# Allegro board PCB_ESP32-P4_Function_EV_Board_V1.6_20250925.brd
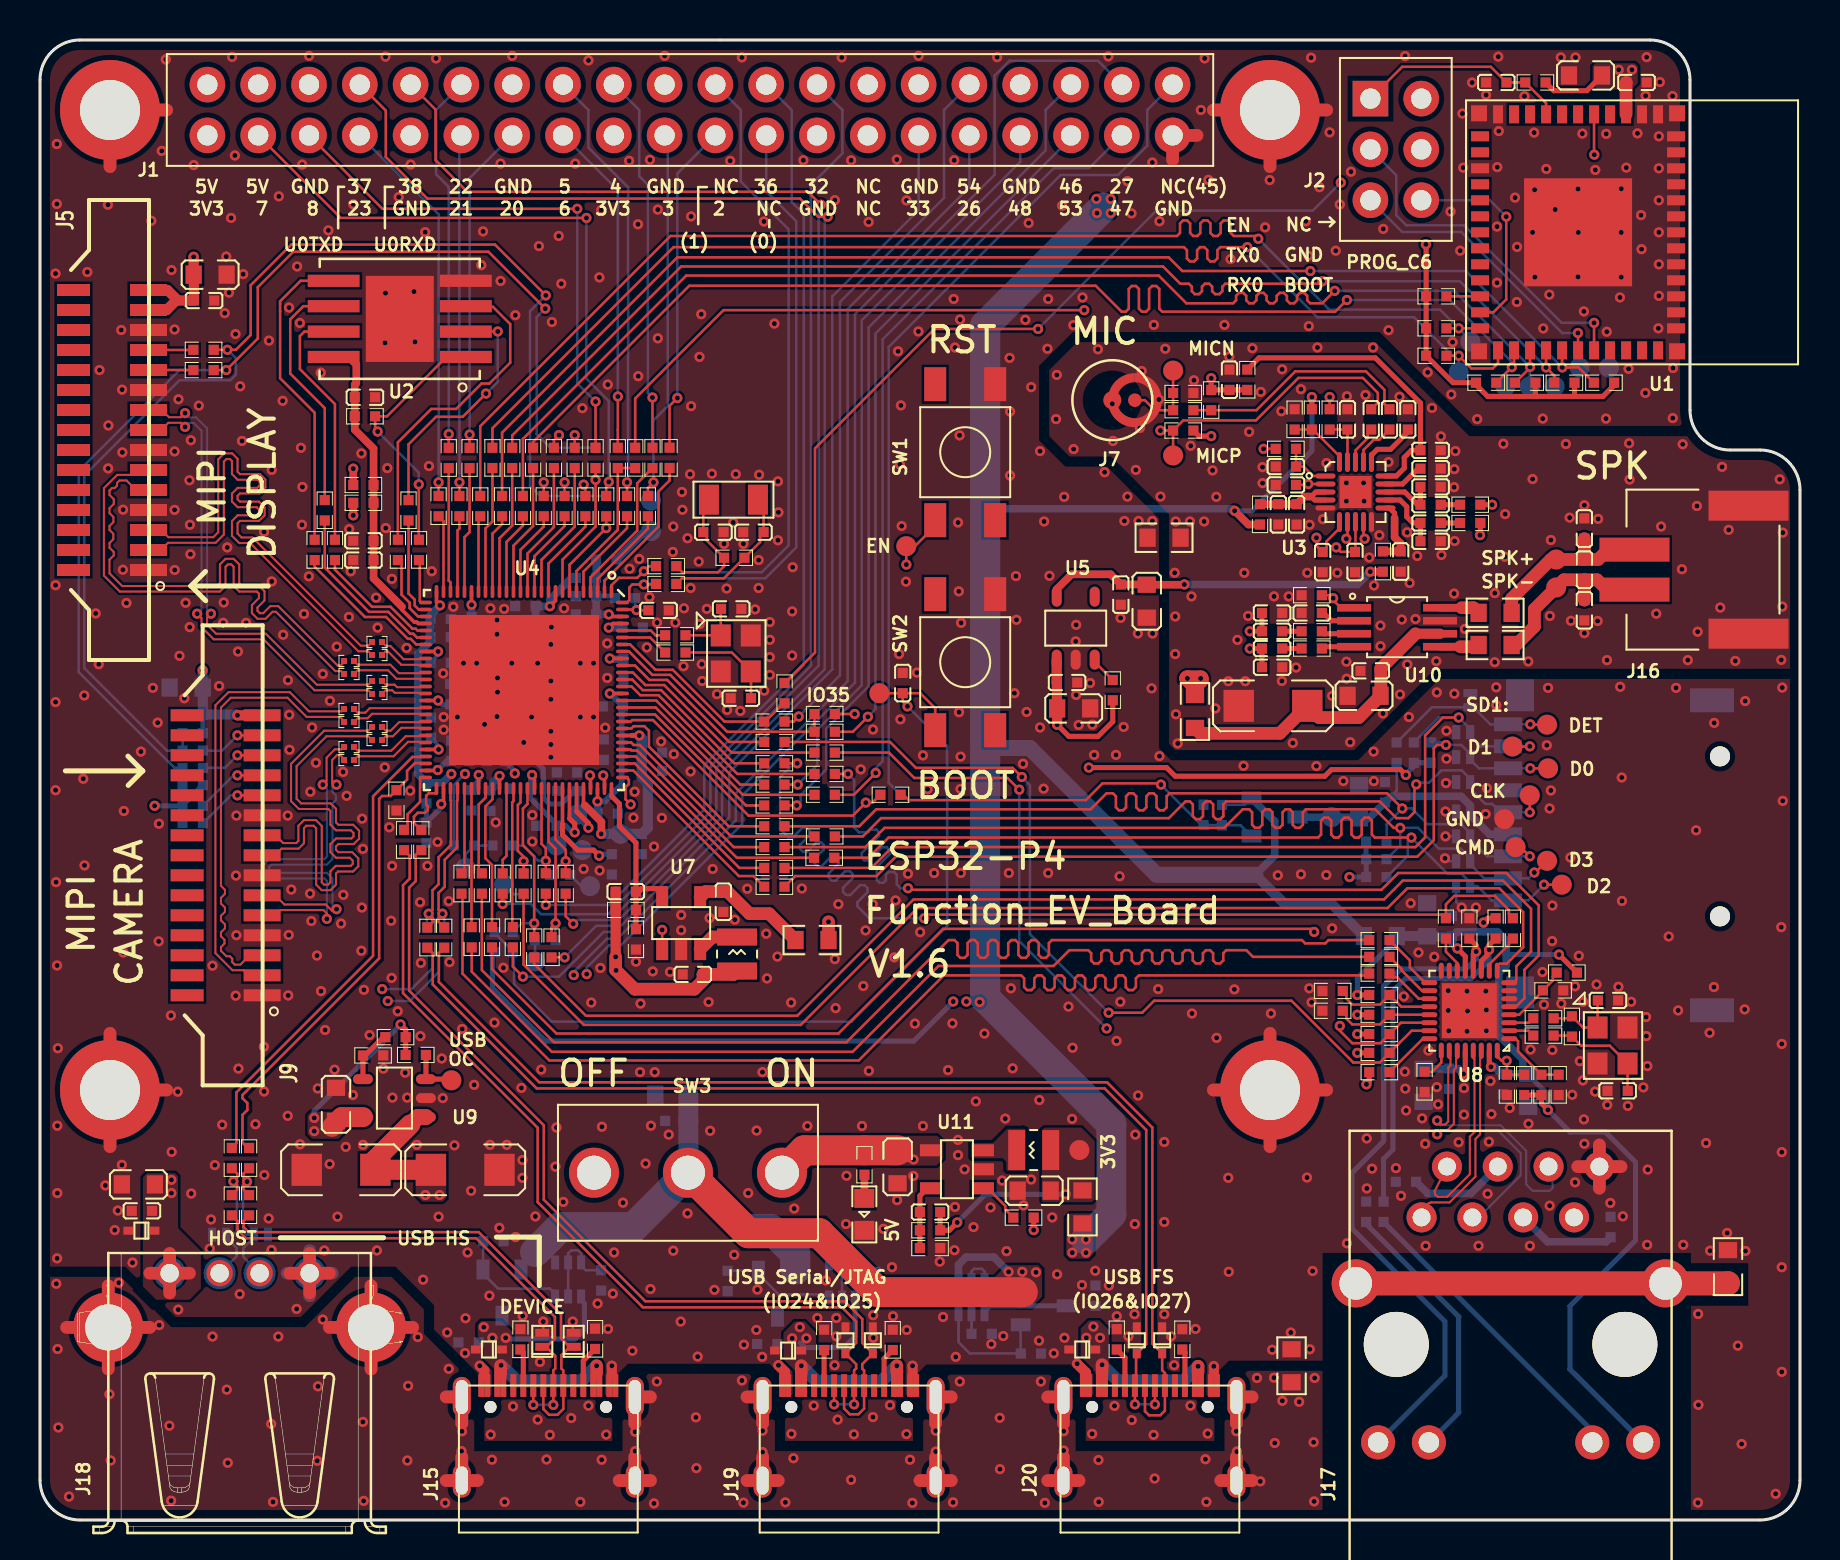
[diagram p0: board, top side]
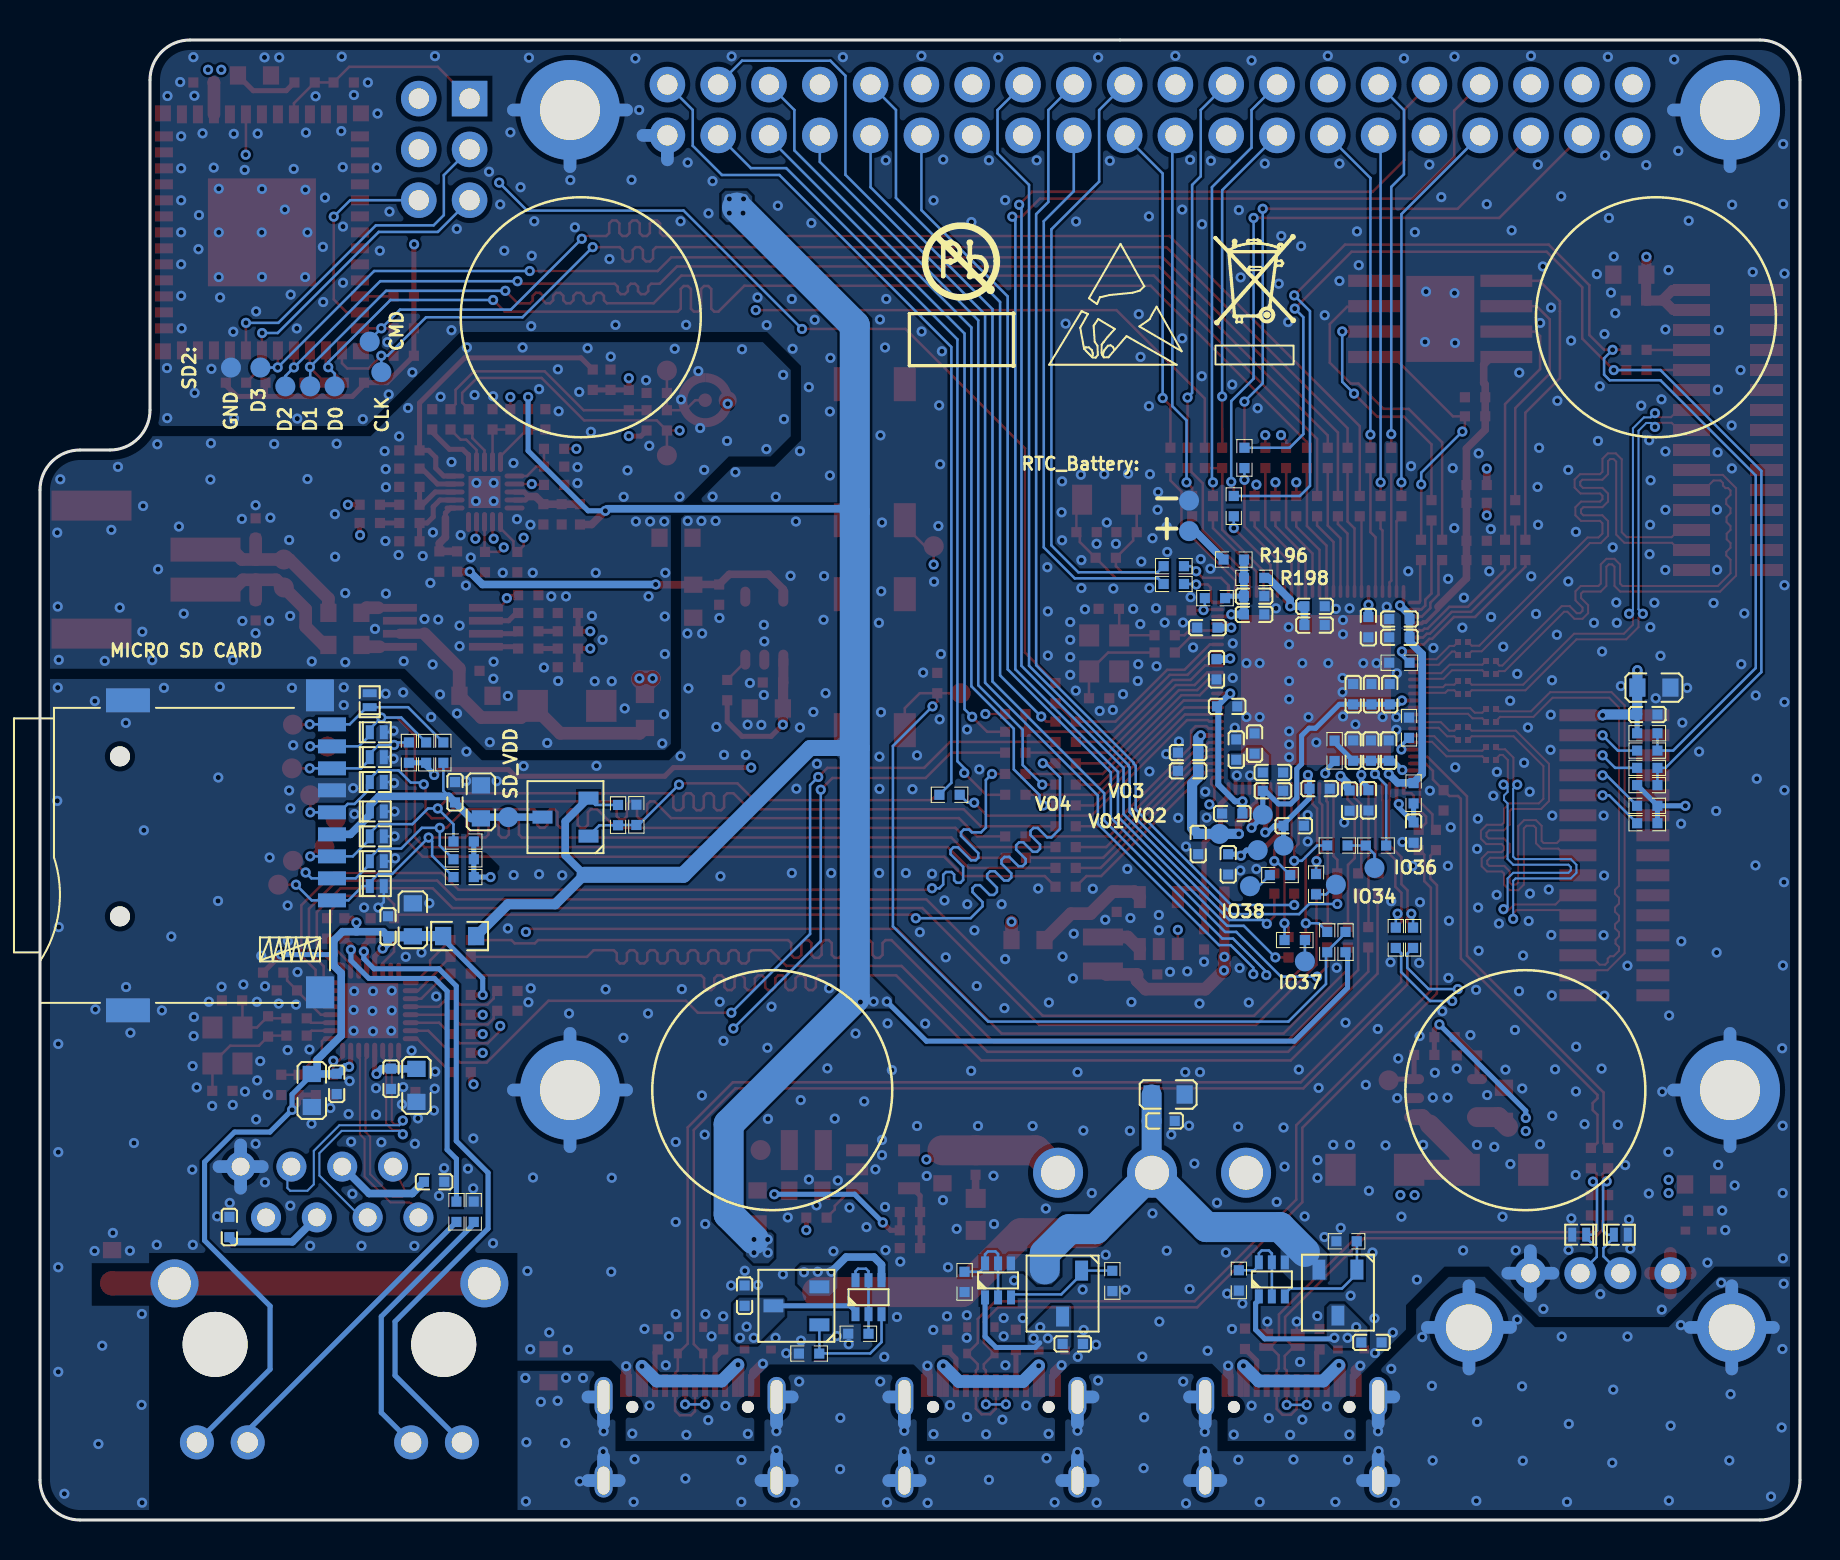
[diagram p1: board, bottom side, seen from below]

Outline 88 x 74 mm; copper layers: TOP, GND, POWER, BOTTOM. Coordinates in mm from the lower left corner of the outline.
Outline path: 0,72 0,2 arc(0.59,0.59) 2,0 86,0 arc(87.41,0.59) 88,2 88,51.5 arc(87.41,52.91) 86,53.5 84.5,53.5 arc(83.09,54.09) 82.5,55.5 82.5,72 arc(81.91,73.41) 80.5,74 2,74 arc(0.59,73.41) 0,72

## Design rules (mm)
net group CSI_A_CLK: nets CSI_CLKN CSI_CLKP
net group CSI_A_DATA0: nets CSI_DATA0N CSI_DATA0P
net group CSI_A_DATA1: nets CSI_DATA1N CSI_DATA1P
net group DP_CSI_A_CLK: nets CSI_A_CLKN CSI_A_CLKP
net group DP_CSI_A_DATA0: nets CSI_A_DATA0N CSI_A_DATA0P
net group DP_CSI_A_DATA1: nets CSI_A_DATA1N CSI_A_DATA1P
net group DP_DSI_A_CLK: nets DSI_A_CLKN DSI_A_CLKP
net group DP_DSI_A_DATA0: nets DSI_A_DATA0N DSI_A_DATA0P
net group DP_DSI_A_DATA1: nets DSI_A_DATA1N DSI_A_DATA1P
net group DP_USB1P1: nets USB1P1_N USB1P1_P
net group DP_USB_DM_C: nets USB_DM_C USB_DP_C
net group DSI_A_CLK: nets DSI_CLKN DSI_CLKP
net group DSI_A_DATA0: nets DSI_DATA0N DSI_DATA0P
net group DSI_A_DATA1: nets DSI_DATA1N DSI_DATA1P
net group RJ_RD: nets RD+ RD-
net group RJ_TD: nets TD+ TD-
net group USB1P1: nets GPIO24 GPIO25

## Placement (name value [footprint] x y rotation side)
C1  10uF/10V(20%)  [C0603]  77.28 72.23 180 top
C2  0.1uF/50V(10%)  [C0402]  79.83 71.88 0 top
C7  10uF/10V(20%)  [C0603]  8.51 62.27 0 top
C8  1uF/16V(10%)  [C0402]  72.81 71.88 180 top
C10  0.1uF/50V(10%)  [C0402]  8.2 60.97 0 top
C14  0.1uF/50V(10%)  [C0402]  67.25 36.39 90 bottom
C15  10uF/10V(20%)  [C0603]  65.95 35.91 90 bottom
C16  0.1uF/50V(10%)  [C0402]  16.25 56.14 0 top
C18  22pF/50V(5%)  [C0402]  33.67 49.39 0 top
C19  22pF/50V(5%)  [C0402]  35.67 49.39 180 top
C20  1uF/16V(10%)  [C0402]  16.17 48.96 180 top
C21  0.1uF/50V(10%)  [C0402]  61.92 50.28 270 top
C22  0.1uF/50V(10%)  [C0402]  62.83 50.28 270 top
C23  22pF/50V(5%)  [C0402]  62.29 51.76 180 top
C24  22pF/50V(5%)  [C0402]  62.29 52.67 180 top
C25  0.1uF/50V(10%)  [C0402]  16.17 48 180 top
C26  22pF/50V(5%)  [C0402]  64.13 47.89 270 top
C27  22pF/50V(5%)  [C0402]  65.37 55.03 90 top
C28  22pF/50V(5%)  [C0402]  34.56 45.56 0 top
C29  22pF/50V(5%)  [C0402]  65.75 47.9 270 top
C30  0.1uF/50V(10%)  [C0402]  30.93 45.48 0 top
C31  10uF/10V(20%)  [C0603]  55.34 45.94 270 top
C32  1uF/16V(10%)  [C0402]  66.56 55.03 270 top
C33  0.1uF/50V(10%)  [C0402]  54.04 46.27 270 top
C34  1uF/16V(10%)  [C0402]  67.48 55.03 270 top
C35  1uF/16V(10%)  [C0402]  68.03 47.92 90 top
C36  1uF/16V(10%)  [C0402]  59.47 57.01 270 top
C37  1uF/16V(10%)  [C0402]  68.39 55.03 270 top
C38  22pF/50V(5%)  [C0402]  69.53 48.94 0 top
C39  1uF/16V(10%)  [C0402]  69.53 49.85 180 top
C40  1uF/16V(10%)  [C0402]  69.53 50.76 180 top
C41  22pF/50V(5%)  [C0402]  69.53 51.65 0 top
C42  1uF/16V(10%)  [C0402]  69.53 52.57 180 top
C43  1uF/16V(10%)  [C0402]  69.53 53.48 0 top
C44  0.1uF/50V(10%)(NC)  [C0402]  43.14 41.85 90 top
C45  22pF/50V(5%)  [C0402]  35.04 41.09 180 top
C46  10uF/10V(20%)  [C0603]  7.31 41.62 180 bottom
C47  0.1uF/50V(10%)  [C0402]  7.64 40.27 180 bottom
C48  0.1uF/50V(10%)  [C0402]  51.35 41.87 0 top
C49  10uF/10V(20%)  [C0603]  51.68 40.58 0 top
C50  1uF/16V(10%)  [C0402]  25.31 34.71 180 bottom
C51  1uF/16V(10%)  [C0402]  30.09 33.8 270 bottom
C53  22pF/50V(5%)(NC)  [C0402]  29.29 31.42 0 top
C54  4.7uF/6.3V(20%)  [C0402]  34.17 30.91 270 top
C55  1uF/16V(10%)  [C0402]  26.35 36.46 180 bottom
C56  1uF/16V(10%)  [C0402]  28.59 32.78 270 bottom
C57  22pF/50V(5%)  [C0402]  61.61 42.64 0 top
C58  0.1uF/50V(10%)  [C0402]  61.61 43.57 0 top
C59  0.1uF/50V(10%)  [C0402]  61.61 44.44 0 top
C60  22pF/50V(5%)  [C0402]  61.61 45.35 0 top
C61  22uF/6.3V(20%)  [C0402]  32.64 27.28 180 top
C62  1uF/16V(10%)  [C0402]  63.59 45.35 180 top
C63  100uF/10V(20%)  [C1206]  61.65 40.71 180 top
C64  20pF/50V(5%)  [C0402]  78.4 25.98 0 top
C65  10uF/10V(20%)  [C0603]  14.8 20.79 90 top
C66  1uF/16V(10%)  [C0402]  66.53 42.46 180 top
C67  10uF/10V(20%)(NC)  [C0603]  66.2 41.21 0 top
C68  20pF/50V(5%)  [C0402]  78.88 21.46 180 top
C69  22pF/50V(5%)(NC)  [C0402]  44.5 15.4 180 top
C70  10uF/10V(20%)  [C0603]  49.71 16.47 180 top
C71  10uF/10V(20%)  [C0603]  42.88 17.66 270 top
C72  100uF/10V(20%)  [C1206]  15.05 17.51 180 top
C73  10uF/10V(20%)  [C0603]  4.92 16.78 180 top
C74  0.1uF/50V(10%)  [C0402]  5.1 15.46 180 top
C75  100uF/10V(20%)  [C1206]  21.26 17.51 0 top
C76  1uF/16V(10%)  [C0402]  52.77 11.22 90 bottom
C77  330pF/50V(10%)(NC)  [C0402]  77.22 49.58 270 top
C78  330pF/50V(10%)(NC)  [C0402]  77.22 47.52 90 top
C79  22uF/10V(20%)  [C0603]  31.59 21.28 180 bottom
C80  0.1uF/50V(10%)  [C0402]  31.77 19.95 180 bottom
C81  330pF/50V(10%)(NC)  [C0402]  77.22 45.49 270 top
C82  10uF/6.3V(20%)  [C0402]  27.3 46.19 180 bottom
C83  0.1uF/50V(10%)  [C0402]  24.27 45.68 180 bottom
C84  0.1uF/50V(10%)  [C0402]  27.3 45.28 180 bottom
C85  0.1uF/50V(10%)  [C0402]  29.63 44.62 0 bottom
C86  0.1uF/50V(10%)  [C0402]  20.03 45.05 0 bottom
C87  10uF/6.3V(20%)  [C0402]  24.27 44.74 180 bottom
C88  0.1uF/50V(10%)  [C0402]  21.58 44.64 270 bottom
C89  0.1uF/50V(10%)  [C0402]  20.03 44.14 0 bottom
C90  0.1uF/50V(10%)  [C0402]  29.18 42.54 270 bottom
C91  1uF/16V(10%)  [C0402]  22.34 41.29 90 bottom
C92  0.1uF/50V(10%)  [C0402]  21.43 41.29 90 bottom
C93  10nF/50V(10%)  [C0402]  20.51 41.29 90 bottom
C94  0.1uF/50V(10%)  [C0402]  28.64 40.68 180 bottom
C95  10uF/6.3V(20%)  [C0402]  28.19 38.52 90 bottom
C96  0.1uF/50V(10%)  [C0402]  27.27 38.82 90 bottom
C97  0.1uF/50V(10%)  [C0402]  22.52 35.97 270 bottom
C98  4.7uF/6.3V(20%)  [C0402]  22.34 38.47 90 bottom
C99  0.1uF/50V(10%)  [C0402]  21.45 38.47 90 bottom
C100  10nF/50V(10%)  [C0402]  20.56 38.47 90 bottom
C101  0.1uF/50V(10%)  [C0402]  30.59 38.37 0 bottom
C102  10uF/6.3V(20%)  [C0402]  30.59 37.46 0 bottom
C103  0.1uF/50V(10%)  [C0402]  26.35 37.38 180 bottom
C104  1uF/16V(10%)  [C0402]  24.02 36.57 180 bottom
C105  0.1uF/50V(10%)  [C0402]  21.58 35.98 270 bottom
C107  10uF/6.3V(20%)  [C0402]  28.39 35.32 0 bottom
C108  10uF/10V(20%)  [C0603]  69.36 30.01 90 bottom
C109  0.1uF/50V(10%)  [C0402]  70.6 29.68 90 bottom
C110  1uF/16V(10%)  [C0402]  21.43 8.88 180 bottom
C111  0.1uF/50V(10%)  [C0402]  70.45 22.06 270 bottom
C112  0.1uF/50V(10%)  [C0402]  73.17 21.81 270 bottom
C113  10uF/10V(20%)  [C0603]  69.18 21.73 270 bottom
C114  10uF/10V(20%)  [C0603]  74.41 21.48 270 bottom
C115  0.1uF/50V(10%)  [C0402]  68.3 16.91 180 bottom
C116  0.1uF/50V(10%)  [C0402]  78.53 14.65 90 bottom
C117  1uF/16V(10%)  [C0402]  36.36 8.8 180 bottom
C118  0.1uF/50V(10%)  [C0402]  19.32 34.37 270 bottom
D3  BSDFN2C031U  [SOD882]  71.16 35.43 0 bottom
D4  BSDFN2C031U  [SOD882]  71.16 34.18 0 bottom
D5  BSDFN2C031U  [SOD882]  71.52 40.99 270 bottom
D6  BSDFN2C031U  [SOD882]  71.16 36.9 0 bottom
D7  BSDFN2C031U  [SOD882]  71.16 32.94 0 bottom
D8  BSDFN2C031U  [SOD882]  71.16 31.69 0 bottom
D10  BSDFN2C031U  [SOD882]  71.16 39.39 0 bottom
D11  BSDFN2C031U  [SOD882]  71.16 38.14 0 bottom
D12  RED LED  [LED0603]  41.21 15.28 90 top
D13  LESD5D5.0CT1G  [SOD523]  22.44 8.52 0 top
D14  ESD7951ST5G  [SOD882]  25.11 9.01 270 top
D15  LESD5D5.0CT1G  [SOD523]  5.07 14.47 0 top
D16  ESD7951ST5G  [SOD882]  26.69 9.01 270 top
D17  LESD5D5.0CT1G  [SOD523]  40.27 8.98 270 top
D18  LESD5D5.0CT1G  [SOD523]  41.64 8.98 270 top
D19  LESD5D5.0CT1G  [SOD523]  37.4 8.47 0 top
D20  LESD5D5.0CT1G  [SOD523]  52.11 8.52 0 top
D21  ESD7951ST5G(NC)  [SOD882]  11.04 14.27 180 bottom
D22  ESD7951ST5G(NC)  [SOD882]  8.96 14.26 0 bottom
D23  LESD5D5.0CT1G  [SOD523]  56.11 8.98 270 top
D24  LESD5D5.0CT1G  [SOD523]  54.84 8.98 270 top
H1  STD  [HOLE5_3]  3.5 70.5 0 top
H2  STD  [HOLE5_3]  61.5 70.5 0 top
H3  STD  [HOLE5_3]  3.5 21.5 0 top
H4  STD  [HOLE5_3]  61.5 21.5 0 top
J1  CON20X2  [CON20X2_2P54]  32.5 70.5 0 top
J2  CON3X2  [CON3X2_2P54]  67.79 68.53 270 top
J5  DSI_1-1734248-5  [FFC_15P_1_MIPI]  3.55 54.5 270 top
J7  MIC_ELECT  [MIC2_4_B4013AM422-042]  53.62 55.99 90 top
J9  CSI_1-1734248-5  [FFC_15P_1_MIPI]  9.23 33.23 270 top
J15  -  [USB_TYPEC_16P_F]  25.42 5.65 0 top
J16  A2001WR-S-2P  [CON2X1_2P0_SMT_PH2A-S-A]  79.72 47.52 90 top
J17  RJ45_HR913550A  [RJ45_HR913129A]  73.53 8.78 180 top
J18  USB-02  [292303-6]  9.98 9.63 0 top
J19  -  [USB_TYPEC_16P_F]  40.46 5.65 0 top
J20  -  [USB_TYPEC_16P_F]  55.5 5.65 0 top
J21  TF_CARD  [TF_CARDA]  84 34.18 0 bottom
L1  2.2uH  [L2520]  34.85 28.3 270 top
L2  0(1%)  [R0603]  72.76 43.75 180 top
L3  0(1%)  [R0603]  72.76 45.36 180 top
L4  2.2uH  [L2520]  49.68 18.5 0 top
NOREF  -  []  0 0 90 top
NOREF#2  -  []  86 53.5 90 top
NOREF#3  -  []  0 0 0 top
NOREF#4  -  []  0 72 0 top
Q2  LMBT3906DW1T1G  [SOT-363]  46.57 11.14 90 bottom
Q3  AO3401A  [SOT23-3]  50.18 10.71 0 bottom
Q4  AO3401A  [SOT23-3]  23.1 11.37 270 bottom
Q5  LMBT3906DW1T1G  [SOT-363]  26.41 12.03 90 bottom
Q6  LMBT3906DW1T1G  [SOT-363]  40.1 11.98 90 bottom
Q7  AO3401A  [SOT23-3]  36.87 11.32 270 bottom
Q8  AO3401A  [SOT23-3]  61.73 35.14 0 bottom
R1  51K(1%)  [R0402]  78.2 56.87 180 top
R3  51K(1%)  [R0402]  76.22 56.87 180 top
R4  10K(1%)  [R0402]  74.77 71.88 0 top
R5  51K(1%)  [R0402]  74.26 56.87 180 top
R6  51K(1%)  [R0402]  72.31 56.87 0 top
R8  0(1%)  [R0402]  8.18 58.51 180 top
R9  0(1%)  [R0402]  8.18 57.49 180 top
R10  10K(1%)  [R0402]  69.81 61.18 180 top
R11  51K(1%)  [R0402]  69.81 59.58 0 top
R12  51K(1%)  [R0402]  69.81 58.21 0 top
R16  51K(1%)  [R0402]  67.83 38.37 90 bottom
R17  51K(1%)  [R0402]  66.82 33.92 0 bottom
R18  10K(1%)  [R0402]  16.25 55.18 180 top
R19  51K(1%)  [R0402]  66.82 33.04 0 bottom
R21  51K(1%)  [R0402]  66.82 32.15 0 bottom
R22  0(1%)  [R0402]  31.48 53.11 270 top
R23  0(1%)  [R0402]  22.62 53.1 270 top
R24  0(1%)  [R0402]  23.61 53.1 270 top
R25  0(1%)  [R0402]  24.65 53.1 270 top
R26  0(1%)  [R0402]  25.69 53.1 270 top
R27  0(1%)  [R0402]  26.74 53.1 270 top
R28  0(1%)  [R0402]  27.78 53.1 270 top
R29  0(1%)  [R0402]  28.89 53.1 270 top
R30  0(1%)  [R0402]  29.76 53.1 90 top
R31  0(1%)  [R0402]  30.62 53.1 270 top
R32  0(1%)  [R0402]  20.44 53.1 270 top
R33  0(1%)  [R0402]  21.48 53.1 270 top
R34  51K(1%)  [R0402]  68.69 38.37 90 bottom
R35  0(1%)(NC)  [R0402]  16.17 51.75 0 top
R36  51K(1%)  [R0402]  69.55 38.37 90 bottom
R37  0(1%)  [R0402]  16.17 50.86 0 top
R38  0(1%)  [R0402]  19.93 50.69 270 top
R39  0(1%)  [R0402]  20.97 50.69 270 top
R40  0(1%)  [R0402]  22.01 50.69 270 top
R41  0(1%)  [R0402]  23.1 50.69 270 top
R42  0(1%)  [R0402]  24.15 50.69 270 top
R43  0(1%)  [R0402]  25.19 50.69 270 top
R44  0(1%)  [R0402]  26.23 50.69 270 top
R45  0(1%)  [R0402]  27.27 50.69 270 top
R46  0(1%)  [R0402]  28.31 50.69 270 top
R47  0(1%)  [R0402]  29.35 50.69 270 top
R48  0(1%)  [R0402]  30.39 50.69 270 top
R49  0(1%)  [R0402]  14.24 50.49 270 top
R50  0(1%)  [R0402]  18.43 50.49 270 top
R51  0(1%)  [R0402]  61 50.28 90 top
R52  0(1%)  [R0402]  62.29 53.56 0 top
R53  0(1%)  [R0402]  13.73 48.5 270 top
R54  0(1%)  [R0402]  14.75 48.5 270 top
R55  0(1%)  [R0402]  17.89 48.5 270 top
R56  0(1%)  [R0402]  18.95 48.5 270 top
R57  10K(1%)  [R0402]  62.73 55.03 270 top
R58  10M(1%)(NC)  [R0402]  34.71 48.11 180 top
R59  0(1%)  [R0402]  31.31 47.69 0 top
R60  10K(1%)(NC)  [R0402]  63.59 55.03 90 top
R61  0(1%)  [R0402]  31.31 46.8 0 top
R62  0(1%)  [R0402]  64.48 55.03 270 top
R63  2.2K(1%)  [R0402]  57.16 54.47 0 top
R64  0(1%)(NC)  [R0402]  57.16 55.49 0 top
R65  2.2K(1%)  [R0402]  58.56 56 90 top
R66  0(1%)  [R0402]  57.16 56.35 0 top
R67  0(1%)  [R0402]  31.77 44.24 0 top
R68  0(1%)  [R0402]  67.15 47.92 270 top
R69  0(1%)  [R0201]  16.85 43.9 0 top
R70  0(1%)  [R0402]  31.77 43.37 0 top
R71  0(1%)  [R0201]  16.85 43.25 0 top
R72  0(1%)  [R0201]  15.45 42.95 0 top
R73  200(1%)  [R0402]  60.36 57.01 90 top
R74  0(1%)  [R0201]  15.45 42.3 0 top
R75  0(1%)  [R0201]  16.85 41.95 0 top
R76  0(1%)  [R0402]  37.23 41.34 90 top
R77  0(1%)  [R0201]  16.85 41.3 0 top
R78  100(1%)  [R0201]  15.45 40.55 180 top
R79  0(1%)  [R0402]  39.23 40.3 0 top
R80  0(1%)  [R0402]  36.72 39.92 180 top
R81  100(1%)  [R0201]  15.45 39.9 180 top
R82  100(1%)  [R0201]  16.85 39.65 180 top
R83  0(1%)  [R0402]  71.51 49.85 0 top
R84  0(1%)  [R0402]  71.51 50.76 0 top
R85  0(1%)  [R0402]  39.23 39.41 180 top
R86  100(1%)  [R0201]  16.85 39 180 top
R87  0(1%)  [R0402]  36.72 38.9 0 top
R88  100(1%)  [R0201]  15.45 38.65 180 top
R89  0(1%)  [R0402]  39.23 38.37 0 top
R90  100(1%)  [R0201]  15.45 38 180 top
R91  0(1%)  [R0402]  36.72 37.84 0 top
R92  0(1%)  [R0402]  39.23 37.3 0 top
R93  0(1%)  [R0402]  36.72 36.77 0 top
R94  0(1%)  [R0402]  39.23 36.26 0 top
R97  0(1%)  [R0402]  36.72 35.73 0 top
R98  2.2K(1%)  [R0402]  7.64 39.33 180 bottom
R99  0(1%)  [R0603]  56.2 49.11 180 top
R100  0(1%)(NC)  [R0402]  42.52 36.26 0 bottom
R101  0(1%)  [R0402]  7.64 38.47 0 bottom
R102  0(1%)  [R0402]  36.72 34.69 0 top
R103  0(1%)  [R0402]  39.23 34.18 0 top
R104  33(1%)  [R0402]  18.2 34 270 top
R105  33(1%)  [R0402]  19.07 34 270 top
R106  0(1%)  [R0402]  7.64 37.61 0 bottom
R107  0(1%)  [R0402]  36.72 33.65 0 top
R108  0(1%)  [R0402]  39.21 33.11 0 top
R109  2.2K(1%)  [R0402]  7.64 36.74 180 bottom
R110  0(1%)  [R0402]  36.72 32.6 0 top
R111  10K(1%)(NC)  [R0402]  7.64 35.71 0 bottom
R112  0(1%)  [R0402]  25.29 31.82 270 top
R113  33(1%)  [R0402]  19.37 29.12 270 top
R114  0(1%)  [R0402]  21.08 31.82 270 top
R115  0(1%)  [R0402]  22.09 31.82 270 top
R116  0(1%)  [R0402]  23.13 31.82 270 top
R117  0(1%)  [R0402]  24.18 31.82 270 top
R118  0(1%)  [R0402]  26.28 31.82 270 top
R122  0(1%)  [R0402]  36.72 31.66 0 top
R123  10K(1%)  [R0402]  7.64 34.84 0 bottom
R127  0(1%)  [R0603]  38.6 29 180 top
R128  499K(1%)(NC)  [R0402]  29.29 30.51 0 top
R131  33(1%)  [R0402]  20.21 29.12 270 top
R132  0(1%)  [R0402]  21.59 29.14 270 top
R133  0(1%)  [R0402]  22.6 29.14 270 top
R134  0(1%)  [R0402]  23.64 29.14 270 top
R135  0(1%)  [R0402]  24.71 28.64 270 top
R136  0(1%)  [R0402]  25.58 28.64 270 top
R138  499K(1%)(NC)  [R0402]  29.8 29.03 270 top
R139  0(1%)  [R0402]  70.3 29.58 270 top
R140  5.1K(1%)  [R0402]  71.47 29.58 270 top
R141  5.1K(1%)  [R0402]  72.78 29.58 270 top
R142  0(1%)  [R0402]  73.64 29.58 270 top
R143  0(1%)  [R0402]  66.97 29 0 top
R144  0(1%)  [R0402]  66.97 28.16 0 top
R145  10K(1%)  [R0402]  17.78 24.14 180 top
R146  150K(1%)  [R0402]  63.59 43.57 0 top
R147  150K(1%)  [R0402]  63.59 44.44 0 top
R148  10K(1%)  [R0402]  63.59 46.24 180 top
R149  5.1K(1%)  [R0402]  76.34 27.37 180 top
R150  0(1%)  [R0402]  66.97 27.32 0 top
R151  10K(1%)  [R0402]  18.79 23.25 0 top
R152  10K(1%)(NC)  [R0402]  16.65 23.23 180 top
R153  5.1K(1%)(NC)  [R0402]  75.66 26.48 0 top
R154  5.1K(1%)(NC)  [R0402]  64.63 26.45 180 top
R155  5.1K(1%)  [R0402]  66.97 26.25 0 top
R156  5.1K(1%)(NC)  [R0402]  64.63 25.46 180 top
R157  5.1K(1%)  [R0402]  66.97 25.26 0 top
R158  0(1%)  [R0402]  75.17 25.08 0 top
R159  10M(1%)(NC)  [R0402]  76.6 24.68 270 top
R160  1.5K(1%)(NC)  [R0402]  66.97 24.3 0 top
R161  0(1%)  [R0402]  75.17 24.22 0 top
R163  1.5K(1%)  [R0402]  66.97 23.36 0 top
R164  5.1K(1%)(NC)  [R0402]  66.97 22.39 0 top
R165  6.19K(1%)  [R0402]  69.23 21.91 270 top
R166  10K(1%)(NC)  [R0402]  73.34 21.76 270 top
R167  10K(1%)(NC)  [R0402]  74.21 21.76 90 top
R168  5.1K(1%)(NC)  [R0402]  75.07 21.76 90 top
R169  5.1K(1%)  [R0402]  75.93 21.76 270 top
R170  22.1K(1%)  [R0402]  44.5 13.6 0 top
R171  0(1%)  [R0603]  57.75 40.43 90 top
R172  100K(1%)  [R0402]  44.5 14.48 180 top
R173  10K(1%)  [R0402]  49.18 15.12 180 top
R174  0(1%)  [R0603]  52.12 15.65 270 top
R175  5.1K(1%)  [R0402]  41.22 17.77 90 top
R176  10K(1%)  [R0402]  47.08 9.31 180 bottom
R177  51K(1%)  [R0402]  49.55 8.32 180 bottom
R178  0(1%)  [R0402]  9.59 15.74 90 top
R179  0(1%)  [R0402]  10.45 15.74 90 top
R180  5.1K(1%)  [R0402]  24.02 9.03 270 top
R181  0(1%)  [R0603]  84.4 12.67 90 top
R182  5.1K(1%)  [R0402]  27.75 9.06 270 top
R183  5.1K(1%)  [R0402]  42.64 9.01 270 top
R184  5.1K(1%)  [R0402]  39.21 9.01 270 top
R185  5.1K(1%)  [R0402]  53.84 9.03 270 top
R186  5.1K(1%)  [R0402]  57.12 9.03 270 top
R187  0(1%)  [R0603]  62.58 7.71 90 top
R190  0(1%)  [R0402]  27.78 53.1 270 bottom
R194  0(1%)  [R0402]  28.31 50.69 270 bottom
R196  0(1%)(NC)  [R0402]  28.31 48.02 180 bottom
R197  0(1%)(NC)  [R0402]  31.31 47.69 180 bottom
R198  0(1%)  [R0402]  27.3 47.11 0 bottom
R199  0(1%)(NC)  [R0402]  31.31 46.8 180 bottom
R200  10K(1%)  [R0402]  29.25 46.09 0 bottom
R202  4.02K(1%)  [R0402]  20.03 42.86 0 bottom
R203  4.02K(1%)  [R0402]  19.55 39.61 90 bottom
R204  0(1%)  [R0402]  23.13 33.72 180 bottom
R205  0(1%)  [R0402]  24.2 31.79 90 bottom
R206  0(1%)  [R0402]  26 32.25 0 bottom
R207  0(1%)  [R0402]  23.64 28.9 270 bottom
R208  10K(1%)  [R0402]  22.72 28.9 270 bottom
R209  10K(1%)  [R0402]  21.2 33.72 180 bottom
R212  0(1%)  [R0402]  25.26 29 180 bottom
R213  0(1%)  [R0603]  67.02 29.2 0 bottom
R216  51K(1%)  [R0402]  22.67 13.93 180 bottom
R217  10K(1%)  [R0402]  28.06 11.98 90 bottom
R220  0(1%)  [R0402]  10.45 18.1 90 top
R221  0(1%)  [R0402]  9.59 18.1 90 top
R222  1K(1%)  [R0402]  67.18 15.41 90 bottom
R223  1K(1%)  [R0402]  66.31 15.41 90 bottom
R224  10K(1%)  [R0402]  41.77 11.9 90 bottom
R225  51K(1%)  [R0402]  34.38 11.95 90 bottom
R226  10K(1%)  [R0402]  53.64 41.49 270 top
R227  33(1%)  [R0402]  20.21 29.11 270 bottom
R228  33(1%)  [R0402]  19.35 29.11 270 bottom
R229  10K(1%)  [R0402]  58.18 35.26 270 bottom
R230  10K(1%)(NC)  [R0402]  59.1 35.25 90 bottom
R231  0(1%)  [R0402]  42.52 36.26 0 top
R232  0(1%)  [R0402]  19.32 36.34 90 bottom
R233  0(1%)  [R0402]  23.27 38.46 270 bottom
R234  1M(1%)(NC)  [R0402]  17.82 35.98 270 top
SW1  SW_SP_4P  [SW4-4P5X4P5X2P9-SMT]  46.26 53.39 270 top
SW2  SW_SP_4P  [SW4-4P5X4P5X2P9-SMT]  46.26 42.89 270 top
SW3  -  [SS-12D10L3]  32.4 17.36 180 top
TP1  TESTPOINT  [TPC1]  30.55 50.97 180 bottom
TP2  TESTPOINT  [TPC1]  30.55 49.44 180 bottom
TP3  TESTPOINT  [TPC1]  78.45 57.62 90 bottom
TP4  TESTPOINT  [TPC1]  71.52 58.92 90 bottom
TP5  TESTPOINT  [TPC1]  70.93 57.39 90 bottom
TP6  TESTPOINT  [TPC1]  76.98 57.62 90 bottom
TP7  TESTPOINT  [TPC1]  75.73 56.68 90 bottom
TP8  TESTPOINT  [TPC1]  74.49 56.68 90 bottom
TP9  TESTPOINT  [TPC1]  73.27 56.68 90 bottom
TP10  TESTPOINT  [TPC1]  75.35 39.77 0 top
TP11  TESTPOINT  [TPC1]  56.66 53.23 90 top
TP12  TESTPOINT  [TPC1]  73.22 35.04 270 top
TP13  TESTPOINT  [TPC1]  64.58 35.14 270 bottom
TP14  TESTPOINT  [TPC1]  73.78 33.65 270 top
TP15  TESTPOINT  [TPC1]  74.49 36.24 270 top
TP16  TESTPOINT  [TPC1]  75.35 32.96 270 top
TP17  TESTPOINT  [TPC1]  76.09 31.77 270 top
TP18  TESTPOINT  [TPC1]  73.63 38.67 270 top
TP19  TESTPOINT  [TPC1]  75.4 37.58 270 top
TP20  TESTPOINT  [TPC1]  56.66 57.47 90 top
TP22  TESTPOINT  [TPC1]  41.97 41.34 180 top
TP23  TESTPOINT  [TPC1]  43.31 48.69 180 top
TP24  TESTPOINT  [TPC1]  25.82 33.72 270 bottom
TP25  TESTPOINT  [TPC1]  29.02 34.31 270 bottom
TP26  TESTPOINT  [TPC1]  27.12 33.49 270 bottom
TP27  TESTPOINT  [TPC1]  26.86 35.27 270 bottom
TP28  TESTPOINT  [TPC1]  20.57 21.98 0 top
TP30  TESTPOINT  [TPC1]  51.97 18.5 0 top
TP31  TESTPOINT  [TPC1]  75.81 46.63 0 top
TP32  TESTPOINT  [TPC1]  75.81 48.02 0 top
TP33  TESTPOINT  [TPC1]  21.28 32.6 180 bottom
TP34  TESTPOINT  [TPC1]  23.21 31.77 180 bottom
TP35  TESTPOINT  [TPC1]  27.5 31.69 180 bottom
TP36  TESTPOINT  [TPC1]  24.76 27.93 180 bottom
U1  -  [ESP32-C6-MINI-1]  71.3 70.98 270 top
U2  FLASH-3V3  [WSON6X8]  17.99 60.05 90 top
U3  ES8311  [QFN20_0P4_3]  65.77 51.4 0 top
U4  ESP32-P4  [QFN104_0P35_10_E7P5_A]  24.2 41.5 270 top
U5  ME6211C33M5G-N  [SOT23-5]  51.78 44.59 90 top
U7  TLV62569  [SOT23_0P95_2P6]  32.06 29.85 90 top
U8  IP101GRI  [QFN32_0P4_4_E2P75]  71.46 25.46 180 top
U9  TPS2051CDBVR  [SOT23-5]  17.72 21.09 180 top
U10  NS4150B  [SSOP8_0P65_5]  67.85 44.64 0 top
U11  TLV62569  [SOT23_0P95_2P6]  45.85 17.54 180 top
Y1  32.768KHz  [XTAL3215]  34.67 51.02 0 top
Y2  40MHz  [XTAL3225]  34.79 43.33 270 top
Y3  25MHz+/-10ppm  [XTAL3225]  78.63 23.73 270 top

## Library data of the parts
C1 C2 C7 C8 C10 C14-C16 C18 C19 C25 C28 C30 C31 C33 C44-C51 C53 C55 C56 C63 C65 C69 C72-C76 C79 C80 C83-C86 C88-C90 C92 C94 C96 C97 C99 C101 C103 C105 C110 C117 C118 = CAPACITOR
C20 C54 C61 C70 C71 C82 C87 C91 C93 C95 C98 C100 C102 C104 C107 = CAP
C21-C24 C26 C27 C29 C32 C34-C43 C57-C60 C62 C64 C66-C68 C77 C78 C81 C108 C109 C111-C116 = CAP NP
D3-D8 D10 D11 D13-D24 = DIODE_BI_DIR
D12 = DIODE_LIGHT
H1-H4 = STD
J1 = CON20X2
J2 = CON3X2
J5 = DSI_1-1734248-5
J7 = MIC_ELECT
J9 = CSI_1-1734248-5
J15 J19 J20 = USB_TYPEC_16P_F
J16 = SPEAKER_0
J17 = RJ45_trans_100_2LED
J18 = USB_0
J21 = TF_SD_SOCKET
L1-L4 = INDUCTOR
Q2 Q5 Q6 = DUAL_PNP
Q3 Q4 Q7 Q8 = PMOS
R1 R3-R6 R8-R12 R16-R19 R21-R50 R53-R56 R58 R59 R61 R67 R69-R72 R74-R82 R85-R94 R97-R118 R122 R123 R127 R128 R131-R136 R138-R145 R149-R161 R163-R170 R172-R187 R190 R194 R196-R200 R202-R209 R212 R213 R216 R217 R220-R234 = RESISTOR
R51 R52 R57 R60 R62-R66 R68 R73 R83 R84 R146-R148 R171 = RESISTOR_0
SW1 SW2 = SW_SP_4P
SW3 = SS-12D10L3
TP1-TP20 TP22-TP27 TP30-TP36 = TESTPOINT
TP28 = TESTPOINT_3
U1 = ESP32-C6-MINI-1
U2 = FLASH_4
U3 = ES8311
U4 = ESP32-P4_QFN104_ECO5
U5 = LDO_SOT23-5_3
U7 U11 = TLV62565
U8 = ESP8080_6
U9 = AP22802_2
U10 = LM25085MY_2
Y1 = XTAL_2P
Y2 = XTAL
Y3 = X1_0

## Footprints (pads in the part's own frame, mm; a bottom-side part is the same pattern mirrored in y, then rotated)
292303-6
  round 1.32 hole 0.92: 1(-3.5,2.71) 2(-1,2.71) 3(1,2.71) 4(3.5,2.71)
  round 3.5 hole 2.3: 5(-6.57,0) 6(6.57,0)
C0402
  rect 0.508x0.508 smd: 1(-0.508,0) 2(0.508,0)
C0603
  rect 0.813x0.914 smd: 1(-0.826,0) 2(0.826,0)
C1206
  rect 1.52x1.6 smd: 1(-1.714,0) 2(1.714,0)
CON2X1_2P0_SMT_PH2A-S-A
  rect 1.2x3.5 smd: 1(1,0) 2(-1,0)
  rect 1.5x4 smd: 3(-3.2,-5.7) 4(3.2,-5.7)
CON3X2_2P54
  rect 1.778x1.778 hole 1.016: 1(-2.54,-1.27)
  round 1.778 hole 1.016: 2(-2.54,1.27) 3(0,-1.27) 4(0,1.27) 5(2.54,-1.27) 6(2.54,1.27)
CON20X2_2P54
  round 1.778 hole 1.016: 1(-24.13,-1.27) 2(-24.13,1.27) 3(-21.59,-1.27) 4(-21.59,1.27) 5(-19.05,-1.27) 6(-19.05,1.27) 7(-16.51,-1.27) 8(-16.51,1.27) 9(-13.97,-1.27) 10(-13.97,1.27) 11(-11.43,-1.27) 12(-11.43,1.27) 13(-8.89,-1.27) 14(-8.89,1.27) 15(-6.35,-1.27) 16(-6.35,1.27) 17(-3.81,-1.27) 18(-3.81,1.27) 19(-1.27,-1.27) 20(-1.27,1.27) 21(1.27,-1.27) 22(1.27,1.27) 23(3.81,-1.27) 24(3.81,1.27) 25(6.35,-1.27) 26(6.35,1.27) 27(8.89,-1.27) 28(8.89,1.27) 29(11.43,-1.27) 30(11.43,1.27) 31(13.97,-1.27) 32(13.97,1.27) 33(16.51,-1.27) 34(16.51,1.27) 35(19.05,-1.27) 36(19.05,1.27) 37(21.59,-1.27) 38(21.59,1.27) 39(24.13,-1.27) 40(24.13,1.27)
ESP32-C6-MINI-1
  rect 0.9x0.5 smd: 1(0.7,9.6) 2(0.7,8.8) 3(0.7,8) 4(0.7,7.2) 5(0.7,6.4) 6(0.7,5.6) 7(0.7,4.8) 8(0.7,4) 9(0.7,3.2) 10(0.7,2.4) 11(0.7,1.6) 25(12.5,1.6) 26(12.5,2.4) 27(12.5,3.2) 28(12.5,4) 29(12.5,4.8) 30(12.5,5.6) 31(12.5,6.4) 32(12.5,7.2) 33(12.5,8) 34(12.5,8.8) 35(12.5,9.6)
  rect 0.5x0.9 smd: 12(1.8,0.7) 13(2.6,0.7) 14(3.4,0.7) 15(4.2,0.7) 16(5,0.7) 17(5.8,0.7) 18(6.6,0.7) 19(7.4,0.7) 20(8.2,0.7) 21(9,0.7) 22(9.8,0.7) 23(10.6,0.7) 24(11.4,0.7) 36(11.4,10.5) 37(10.6,10.5) 38(9.8,10.5) 39(9,10.5) 40(8.2,10.5) 41(7.4,10.5) 42(6.6,10.5) 43(5.8,10.5) 44(5,10.5) 45(4.2,10.5) 46(3.4,10.5) 47(2.6,10.5) 48(1.8,10.5)
  rect 5.4x5.4 smd: 49(6.6,5.6)
  rect 0.8x0.8 smd: 50(12.55,10.55) 51(12.55,0.65) 52(0.65,0.65) 53(0.65,10.55)
FFC_15P_1_MIPI
  rect 0.6x1.85 smd: 1(7,1.875) 2(6,1.875) 3(5,1.875) 4(4,1.875) 5(3,1.875) 6(2,1.875) 7(1,1.875) 8(0,1.875) 9(-1,1.875) 10(-2,1.875) 11(-3,1.875) 12(-4,1.875) 13(-5,1.875) 14(-6,1.875) 15(-7,1.875)
  rect 0.6x1.65 smd: 16(7,-1.875) 17(6,-1.875) 18(5,-1.875) 19(4,-1.875) 20(3,-1.875) 21(2,-1.875) 22(1,-1.875) 23(0,-1.875) 24(-1,-1.875) 25(-2,-1.875) 26(-3,-1.875) 27(-4,-1.875) 28(-5,-1.875) 29(-6,-1.875) 30(-7,-1.875)
HOLE5_3
  round 5 hole 3: 1(0,0)
L2520
  rect 0.85x2 smd: 1(-0.85,0) 2(0.85,0)
LED0603
  rect 0.95x1 smd: 1(0.8,0) 2(-0.8,0)
MIC2_4_B4013AM422-042
  round 0.9 smd: 1(0,0)
  custom 0.675x0.675 smd: 2(0,-1.125)
QFN20_0P4_3
  oval 1x0.25 smd: 1(-1.5,0.8) 2(-1.5,0.4) 3(-1.5,0) 4(-1.5,-0.4) 5(-1.5,-0.8) 11(1.5,-0.8) 12(1.5,-0.4) 13(1.5,0) 14(1.5,0.4) 15(1.5,0.8)
  oval 0.25x1 smd: 6(-0.8,-1.5) 7(-0.4,-1.5) 8(0,-1.5) 9(0.4,-1.5) 10(0.8,-1.5) 16(0.8,1.5) 17(0.4,1.5) 18(0,1.5) 19(-0.4,1.5) 20(-0.8,1.5)
  rect 1.6x1.6 smd: 21(0,0)
QFN32_0P4_4_E2P75
  oval 0.8x0.25 smd: 1(-2,1.4) 2(-2,1) 3(-2,0.6) 4(-2,0.2) 5(-2,-0.2) 6(-2,-0.6) 7(-2,-1) 8(-2,-1.4) 17(2,-1.4) 18(2,-1) 19(2,-0.6) 20(2,-0.2) 21(2,0.2) 22(2,0.6) 23(2,1) 24(2,1.4)
  oval 0.25x0.8 smd: 9(-1.4,-2) 10(-1,-2) 11(-0.6,-2) 12(-0.2,-2) 13(0.2,-2) 14(0.6,-2) 15(1,-2) 16(1.4,-2) 25(1.4,2) 26(1,2) 27(0.6,2) 28(0.2,2) 29(-0.2,2) 30(-0.6,2) 31(-1,2) 32(-1.4,2)
  rect 2.75x2.75 smd: 33(0,0)
QFN104_0P35_10_E7P5_A
  oval 0.65x0.18 smd: 1(-4.925,4.375) 2(-4.925,4.025) 3(-4.925,3.675) 4(-4.925,3.325) 5(-4.925,2.975) 6(-4.925,2.625) 7(-4.925,2.275) 8(-4.925,1.925) 9(-4.925,1.575) 10(-4.925,1.225) 11(-4.925,0.875) 12(-4.925,0.525) 13(-4.925,0.175) 14(-4.925,-0.175) 15(-4.925,-0.525) 16(-4.925,-0.875) 17(-4.925,-1.225) 18(-4.925,-1.575) 19(-4.925,-1.925) 20(-4.925,-2.275) 21(-4.925,-2.625) 22(-4.925,-2.975) 23(-4.925,-3.325) 24(-4.925,-3.675) 25(-4.925,-4.025) 26(-4.925,-4.375) 53(4.925,-4.375) 54(4.925,-4.025) 55(4.925,-3.675) 56(4.925,-3.325) 57(4.925,-2.975) 58(4.925,-2.625) 59(4.925,-2.275) 60(4.925,-1.925) 61(4.925,-1.575) 62(4.925,-1.225) 63(4.925,-0.875) 64(4.925,-0.525) 65(4.925,-0.175) 66(4.925,0.175) 67(4.925,0.525) 68(4.925,0.875) 69(4.925,1.225) 70(4.925,1.575) 71(4.925,1.925) 72(4.925,2.275) 73(4.925,2.625) 74(4.925,2.975) 75(4.925,3.325) 76(4.925,3.675) 77(4.925,4.025) 78(4.925,4.375)
  oval 0.18x0.65 smd: 27(-4.375,-4.925) 28(-4.025,-4.925) 29(-3.675,-4.925) 30(-3.325,-4.925) 31(-2.975,-4.925) 32(-2.625,-4.925) 33(-2.275,-4.925) 34(-1.925,-4.925) 35(-1.575,-4.925) 36(-1.225,-4.925) 37(-0.875,-4.925) 38(-0.525,-4.925) 39(-0.175,-4.925) 40(0.175,-4.925) 41(0.525,-4.925) 42(0.875,-4.925) 43(1.225,-4.925) 44(1.575,-4.925) 45(1.925,-4.925) 46(2.275,-4.925) 47(2.625,-4.925) 48(2.975,-4.925) 49(3.325,-4.925) 50(3.675,-4.925) 51(4.025,-4.925) 52(4.375,-4.925) 79(4.375,4.925) 80(4.025,4.925) 81(3.675,4.925) 82(3.325,4.925) 83(2.975,4.925) 84(2.625,4.925) 85(2.275,4.925) 86(1.925,4.925) 87(1.575,4.925) 88(1.225,4.925) 89(0.875,4.925) 90(0.525,4.925) 91(0.175,4.925) 92(-0.175,4.925) 93(-0.525,4.925) 94(-0.875,4.925) 95(-1.225,4.925) 96(-1.575,4.925) 97(-1.925,4.925) 98(-2.275,4.925) 99(-2.625,4.925) 100(-2.975,4.925) 101(-3.325,4.925) 102(-3.675,4.925) 103(-4.025,4.925) 104(-4.375,4.925)
  rect 7.5x7.5 smd: 105(0,0)
R0201
  rect 0.3x0.3 smd: 1(-0.25,0) 2(0.25,0)
R0402
  rect 0.508x0.508 smd: 1(-0.508,0) 2(0.508,0)
R0603
  rect 0.813x0.914 smd: 1(-0.826,0) 2(0.826,0)
RJ45_HR913129A
  round 3.25 hole 3.25 unplated: (-5.715,0) (5.715,0)
  round 1.5 hole 0.89: 1(4.45,-6.35) 2(3.18,-8.89) 3(1.91,-6.35) 4(0.64,-8.89) 5(-0.63,-6.35) 6(-1.9,-8.89) 7(-3.17,-6.35) 8(-4.44,-8.89)
  round 1.7 hole 1.02: 9(6.625,4.9) 10(4.085,4.9) 11(-4.085,4.9) 12(-6.625,4.9)
  round 2.4 hole 1.63: SHD1(-7.745,-3.05) SHD2(7.745,-3.05)
SOD523
  rect 0.48x0.4 smd: 1(-0.66,0) 2(0.66,0)
SOD882
  rect 0.4x0.7 smd: 1(-0.35,0) 2(0.35,0)
SOT23-3
  rect 1x0.65 smd: 1(-1.15,0.95) 2(-1.15,-0.95) 3(1.15,0)
SOT23-5
  oval 1x0.5 smd: 1(-1.575,0.95) 2(-1.575,0) 3(-1.575,-0.95) 4(1.575,-0.95) 5(1.575,0.95)
SOT23_0P95_2P6
  rect 1.1x0.6 smd: 1(-1.3,0.95) 2(-1.3,0) 3(-1.3,-0.95) 4(1.3,-0.95) 5(1.3,0.95)
SOT-363
  rect 0.7x0.4 smd: 1(-0.85,0.65) 2(-0.85,0) 3(-0.85,-0.65) 4(0.85,-0.65) 5(0.85,0) 6(0.85,0.65)
SS-12D10L3
  round 2.5 hole 1.7: 1(-4.7,0) 2(0,0) 3(4.7,0)
SSOP8_0P65_5
  rect 1.7x0.38 smd: 1(-2.15,0.975) 2(-2.15,0.325) 3(-2.15,-0.325) 4(-2.15,-0.975) 5(2.15,-0.975) 6(2.15,-0.325) 7(2.15,0.325) 8(2.15,0.975)
SW4-4P5X4P5X2P9-SMT
  rect 1.7x1.1 smd: 1(-3.4,1.5) 2(-3.4,-1.5) 3(3.4,-1.5) 4(3.4,1.5)
TF_CARDA
  round 1 hole 1 unplated: (0,-4) (0,4)
  rect 1.4x0.7 smd: 1(-10.6,3.2) 2(-10.6,2.1) 3(-10.6,1) 4(-10.6,-0.1) 5(-10.6,-1.2) 6(-10.6,-2.3) 7(-10.6,-3.4) 8(-10.6,-4.5) 9(-10.6,-5.6)
  rect 1.4x1.6 smd: 10(-10,-7.05) 12(-10,7.8)
  rect 2.2x1.2 smd: 11(-0.4,-6.8) 13(-0.4,8.7)
TPC1
  round 1 smd: 1(0,0)
USB_TYPEC_16P_F
  round 0.6 hole 0.6 unplated: (-2.89,0) (2.89,0)
  rect 0.3x1.14 smd: 1(-3.35,1.07) 2(-3.05,1.07) 3(-2.55,1.07) 4(-2.25,1.07) 5(-1.75,1.07) 6(-1.25,1.07) 7(-0.75,1.07) 8(-0.25,1.07) 9(0.25,1.07) 10(0.75,1.07) 11(1.25,1.07) 12(1.75,1.07) 13(2.25,1.07) 14(2.55,1.07) 15(3.05,1.07) 16(3.35,1.07)
  oval 0.9x1.7 hole 0.6x1.4: 17(-4.325,-3.68) 20(4.325,-3.68)
  oval 0.9x2 hole 0.6x1.7: 18(-4.325,0.5) 19(4.325,0.5)
WSON6X8
  rect 0.61x2.591 smd: 1(-1.905,-3.305) 2(-0.635,-3.305) 3(0.635,-3.305) 4(1.905,-3.305) 5(1.905,3.305) 6(0.635,3.305) 7(-0.635,3.305) 8(-1.905,3.305)
  rect 4.3x3.4 smd: 9(0,0)
XTAL3215
  rect 1x1.5 smd: 1(-1.225,0) 2(1.225,0)
XTAL3225
  rect 1.1x1 smd: 1(-0.9,-0.75) 2(0.9,-0.75) 3(0.9,0.75) 4(-0.9,0.75)

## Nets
A3V3: C31.1 C33.1 R68.2 U5.5(OUT)
AGND: C21.2 C22.2 C23.2 C24.2 C26.2 C27.2 C29.2 C35.1 C36.1 C37.1 C38.2 C41.2 C42.1 C43.2 C57.2 C60.2 C62.2 C63.2 C66.2 C67.1 C77.1 C81.2 J16.3 J16.4 R57.1 R66.2 R99.1 R148.2 U3.5(DGND) U3.10(AGND) U3.21(PAD) U10.7(GND)
AVDD: C35.2 R68.1 U3.11(AVDD)
DVDD: C21.1 C22.1 R51.2 U3.3(PVDD) U3.4(DVDD)
GND: C1.2 C2.2 C7.2 C8.2 C10.2 C14.2 C15.2 C16.2 C18.2 C19.2 C20.2 C25.2 C28.2 C30.2 C31.2 C33.2 C44.2 C45.2 C46.2 C47.2 C48.2 C49.2 C50.2 C51.2 C54.2 C55.2 C56.2 C61.2 C64.2 C65.2 C68.2 C70.2 C71.2 C72.2 C73.2 C74.2 C75.2 C76.2 C79.2 C80.2 C82.2 C83.2 C84.2 C85.2 C86.2 C87.2 C88.2 C89.2 C90.2 C91.2 C92.2 C93.2 C94.2 C95.2 C96.2 C97.2 C98.2 C99.2 C100.2 C101.2 C102.2 C103.2 C104.2 C105.2 C107.2 C108.2 C109.2 C110.2 C111.2 C112.2 C113.2 C114.2 C115.2 C116.2 C117.2 C118.2 D3.1 D4.1 D5.1 D6.1 D7.1 D8.1 D10.1 D11.1 D12.2(CATHODE) D13.1 D14.1 D15.1 D16.1 D17.1 D18.1 D19.1 D20.1 D21.1 D22.1 D23.1 D24.1 H1.1 H2.1 H3.1 H4.1 J1.6 J1.9 J1.14 J1.20 J1.25 J1.30 J1.34 J1.39 J2.4 J5.1(GND#1) J5.4(GND#4) J5.7(GND#7) J5.10(GND#10) J5.13(GND#13) J9.1(GND#1) J9.4(GND#4) J9.7(GND#7) J9.10(GND#10) J15.1(A1_G) J15.2(B12_G) J15.15(B1_G) J15.16(A12_G) J17.8(GND) J18.4(GND#4) J19.1(A1_G) J19.2(B12_G) J19.15(B1_G) J19.16(A12_G) J20.1(A1_G) J20.2(B12_G) J20.15(B1_G) J20.16(A12_G) J21.6(VSS) J21.10(G1) J21.11(G2) J21.12(G3) J21.13(G4) R99.2 R138.2 R140.1 R152.1 R153.2 R154.2 R156.2 R165.2 R166.2 R169.2 R170.2 R176.1 R177.1 R180.1 R181.2 R182.1 R183.1 R184.1 R185.1 R186.1 R187.2 R202.2 R203.2 R216.1 R217.1 R223.2 R224.1 R225.1 R229.1 R234.2 SW1.1 SW2.1 TP1.1 TP3.1 TP12.1 U1.1(GND#1) U1.2(GND#2) U1.11(GND#11) U1.14(GND#14) U1.36(GND#36) U1.37(GND#37) U1.38(GND#38) U1.39(GND#39) U1.40(GND#40) U1.41(GND#41) U1.42(GND#42) U1.43(GND#43) U1.44(GND#44) U1.45(GND#45) U1.46(GND#46) U1.47(GND#47) U1.48(GND#48) U1.49(EPAD) U1.50(GND#50) U1.51(GND#51) U1.52(GND#52) U1.53(GND#53) U2.4(GND) U2.9(EPAD) U4.105(GND) U5.2(GND) U7.2(GND) U8.33(E-PAD) U9.2(GND) U11.2(GND) Y2.2(GND#2) Y2.4(GND#4) Y3.2(GND#2) Y3.4(GND#4)
GND_EARTH: J15.17(E_G1) J15.18(E_G2) J15.19(E_G3) J15.20(E_G4) J18.5(GND#5) J18.6(GND#6) J19.17(E_G1) J19.18(E_G2) J19.19(E_G3) J19.20(E_G4) J20.17(E_G1) J20.18(E_G2) J20.19(E_G3) J20.20(E_G4) R187.1
GND_RJ45_EARTH: J17.SHD1 J17.SHD2 R181.1
VBUS_EN: R145.2 R152.2 U9.4(EN)
VBUS_OUT: C72.1 C73.1 C74.1 C75.1 D15.2 J18.1(VBUS) U9.1(OUT)
VCC_5V: C48.1 C49.1 C65.1 C71.1 J1.2 J1.4 R145.1 R151.1 R171.2 R173.1 R175.2 R226.2 SW3.1 U5.1(VIN) U9.5(IN) U11.4(VIN)
VDD_FLASH: C16.1 C20.1 C25.1 R18.2 R35.2 R37.2 U2.8(VCC) U4.30(VDD_FLASHIO)
25M_XI: R161.1 U8.2(X1)
25M_XO: R158.1 U8.3(X2)
ADCVREF: C43.1 R73.2 U3.15(ADCVREF)
BAT: R196.1 TP2.1
C6_EN: C8.1 J2.1 R4.1 R76.2 U1.8(EN)
C6_IO8: R10.1 U1.22(IO8)
C6_IO9: J2.6 U1.23(IO9)
C6_U0RXD: J2.5 U1.30(RXD0)
C6_U0TXD: J2.3 U1.31(TXD0)
C6_WAKEUP: R30.2 U1.5(IO2)
CNN_GPIO0: J1.23 R199.1
CNN_GPIO1: J1.22 R197.1
CNN_GPIO2: J1.21 R22.1
CNN_GPIO3: J1.19 R48.1
CNN_GPIO4: J1.18 R31.1
CNN_GPIO5: J1.16 R47.1
CNN_GPIO6: J1.15 R29.1
CNN_GPIO7: J1.3 R46.1
CNN_GPIO8: J1.5 R28.1
CNN_GPIO20: J1.13 R33.1
CNN_GPIO21: J1.11 R39.1
CNN_GPIO22: J1.12 R32.1
CNN_GPIO23: J1.7 R38.1
CNN_GPIO26: J1.31 R228.2
CNN_GPIO27: J1.38 R227.2
CNN_GPIO32: J1.26 R116.2
CNN_GPIO33: J1.29 R134.2
CNN_GPIO36: J1.24 R112.2
CNN_GPIO37: J1.8 R136.2
CNN_GPIO38: J1.10 R118.2
CNN_GPIO45: J1.40 R100.2
CNN_GPIO46: J1.36 R97.2
CNN_GPIO47: J1.37 R94.2
CNN_GPIO48: J1.33 R93.2
CNN_GPIO53: J1.35 R85.1
CNN_GPIO54: J1.32 R80.1
CODEC_CE: R57.2 R60.1 U3.20(CE)
COL: R149.2 R153.1 U8.4(COL/RMII)
CRS: R154.1 R155.2 U8.20(CRS/LEDMOD)
CSI_A_CLKN: J9.8(CLK_CN) R86.2
CSI_A_CLKP: J9.9(CLK_CP) R82.2
CSI_A_DATA0N: J9.2(DN0) R78.2
CSI_A_DATA0P: J9.3(DP0) R81.2
CSI_A_DATA1N: J9.5(DN1) R88.2
CSI_A_DATA1P: J9.6(DP1) R90.2
CSI_CLKN: R86.1 U4.45(CSI_CLKN)
CSI_CLKP: R82.1 U4.44(CSI_CLKP)
CSI_DATA0N: R78.1 U4.42(CSI_DATAN0)
CSI_DATA0P: R81.1 U4.43(CSI_DATAP0)
CSI_DATA1N: R88.1 U4.46(CSI_DATAN1)
CSI_DATA1P: R90.1 U4.47(CSI_DATAP1)
CSI_IO0: J9.11(CAM_IO0) R123.2
CSI_IO1: J9.12(CAM_IO1) R111.2
CSI_REXT: R203.1 U4.48(CSI_REXT)
DACVREF: C42.2 U3.14(DACVREF)
DSI_A_CLKN: J5.5(CLK_CN) R72.1
DSI_A_CLKP: J5.6(CLK_CP) R74.1
DSI_A_DATA0N: J5.8(DN0) R77.1
DSI_A_DATA0P: J5.9(DP0) R75.1
DSI_A_DATA1N: J5.2(DN1) R71.1
DSI_A_DATA1P: J5.3(DP1) R69.1
DSI_CLKN: R72.2 U4.37(DSI_CLKN)
DSI_CLKP: R74.2 U4.38(DSI_CLKP)
DSI_DATA0N: R77.2 U4.40(DSI_DATAN0)
DSI_DATA0P: R75.2 U4.39(DSI_DATAP0)
DSI_DATA1N: R71.2 U4.36(DSI_DATAN1)
DSI_DATA1P: R69.2 U4.35(DSI_DATAP1)
DSI_REXT: R202.1 U4.34(DSI_REXT)
EN_DCDC: U4.79(EN_DCDC) U7.1(EN/PG)
ESP_3V3: C1.1 C2.1 C7.1 C10.1 C46.1 C47.1 C83.1 C85.1 C87.1 C88.1 C90.1 C95.1 C96.1 C97.1 C103.1 J1.1 J1.17 J5.14(3V3#14) J5.15(3V3#15) J9.15(3V3) Q8.2(S) R1.1 R3.1 R4.2 R5.1 R6.1 R10.2 R11.1 R12.1 R35.1 R51.1 R60.2 R98.1 R109.1 R111.1 R123.1 R127.1 R174.2 R198.1 R208.2 R209.2 R213.1 R230.2 R233.2 U1.3(3V3) U4.9(VDD_LP) U4.21(VDD_IO_0) U4.62(VDD_IO_4) U4.75(VDD_LDO) U4.77(VDD_DCDCC) U4.96(VDD_IO_6) U4.101(VDD_ANA)
ESP_EN: C30.1 R200.2 SW1.3 TP23.1 U4.103(CHIP_PU)
ESP_I2C_SCL: R9.1 R52.1 R106.1 R109.2 R190.1
ESP_I2C_SDA: R8.1 R62.1 R98.2 R101.1 R194.1
ESP_LDO_VO1: C56.1 R37.1 TP26.1 U4.71(VDDO_FLASH)
ESP_LDO_VO2: C50.1 C104.1 C105.1 TP24.1 U4.59(VDD_PSRAM_0) U4.67(VDD_PSRAM_1) U4.72(VDDO_PSRAM)
ESP_LDO_VO3: C55.1 C91.1 C92.1 C93.1 TP27.1 U4.41(VDD_MIPI_DPHY) U4.73(VDDO_3)
ESP_LDO_VO4: C51.1 C101.1 C102.1 R17.1 R19.1 R21.1 R34.1 R36.1 TP25.1 U4.74(VDDO_4) U4.85(VDD_IO_5)
ESP_VBAT: C82.1 C84.1 R196.2 R198.2 R200.1 U4.102(VDD_BAT)
ESP_VDD_HP: C53.1 C61.1 C86.1 C89.1 C94.1 C107.1 L1.2 R128.1 R232.2 U4.26(VDD_HP_0) U4.76(VDD_HP_2) U4.91(VDD_HP_3)
FB_DCDC: C53.2 R128.2 R138.1 U4.78(FB_DCDC) U7.5(FB)
FLASH_CK: R49.2 U4.32(FLASH_CK)
FLASH_CK_A: R49.1 U2.6(CLK)
FLASH_CS: R56.2 U4.27(FLASH_CS)
FLASH_CS_A: R18.1 R56.1 U2.1(/CS)
FLASH_D: R53.2 U4.33(FLASH_D)
FLASH_D_A: R53.1 U2.5(DI)
FLASH_HD: R54.2 U4.31(FLASH_HOLD)
FLASH_HD_A: R54.1 U2.7(/HOLD)
FLASH_Q: R50.2 U4.28(FLASH_Q)
FLASH_Q_A: R50.1 U2.2(DO)
FLASH_WP: R55.2 U4.29(FLASH_WP)
FLASH_WP_A: R55.1 U2.3(/WP)
GPIO0: R61.1 R199.2 U4.104(GPIO0)
GPIO1: R59.1 R197.2 U4.1(GPIO1)
GPIO2: R22.2 U4.2(GPIO2)
GPIO3: R48.2 U4.3(GPIO3)
GPIO4: R31.2 U4.4(GPIO4)
GPIO5: R47.2 U4.5(GPIO5)
GPIO6: R29.2 R30.1 U4.6(GPIO6)
GPIO7: R46.2 R194.2 U4.7(GPIO7)
GPIO8: R28.2 R190.2 U4.8(GPIO8)
GPIO9: R45.2 U4.10(GPIO9)
GPIO10: R27.2 U4.11(GPIO10)
GPIO11: R44.2 U4.12(GPIO11)
GPIO12: R26.2 U4.13(GPIO12)
GPIO13: R43.2 U4.14(GPIO13)
GPIO14: R25.2 U4.15(GPIO14)
GPIO15: R42.2 U4.16(GPIO15)
GPIO16: R24.2 U4.17(GPIO16)
GPIO17: R41.2 U4.18(GPIO17)
GPIO18: R23.2 U4.19(GPIO18)
GPIO19: R40.2 U4.20(GPIO19)
GPIO20: R33.2 U4.22(GPIO20)
GPIO21: R39.2 U4.23(GPIO21)
GPIO22: R32.2 U4.24(GPIO22)
GPIO23: R38.2 U4.25(GPIO23)
GPIO24: R104.1 U4.52(GPIO24)
GPIO25: R105.1 U4.53(GPIO25)
GPIO26: R113.1 R228.1 U4.55(GPIO26)
GPIO27: R131.1 R227.1 U4.56(GPIO27)
GPIO28: R114.1 U4.57(GPIO28)
GPIO29: R132.1 U4.58(GPIO29)
GPIO30: R115.1 U4.60(GPIO30)
GPIO31: R133.1 U4.61(GPIO31)
GPIO32: R116.1 U4.63(GPIO32)
GPIO33: R134.1 U4.64(GPIO33)
GPIO34: R117.1 R205.2 U4.65(GPIO34)
GPIO34_BOOTMODE: R205.1 TP34.1
GPIO35: R135.1 R207.1 U4.66(GPIO35)
GPIO35_BOOTMODE: C44.1 R207.2 R208.1 SW2.3 TP22.1
GPIO36: R112.1 R204.1 U4.68(GPIO36)
GPIO36_BOOTMODE: R204.2 R209.1 TP33.1
GPIO37: R136.1 R212.1 U4.69(GPIO37)
GPIO37_BOOTMODE: R212.2 TP36.1
GPIO38: R118.1 R206.1 U4.70(GPIO38)
GPIO38_BOOTMODE: R206.2 TP35.1
GPIO39: R122.1 U4.80(GPIO39)
GPIO40: R110.1 U4.81(GPIO40)
GPIO41: R108.1 U4.82(GPIO41)
GPIO42: R107.1 U4.83(GPIO42)
GPIO43: R103.1 U4.84(GPIO43)
GPIO44: R102.1 U4.86(GPIO44)
GPIO45: R100.1 R231.1 U4.87(GPIO45)
GPIO46: R97.1 U4.88(GPIO46)
GPIO47: R94.1 U4.89(GPIO47)
GPIO48: R93.1 U4.90(GPIO48)
GPIO49: R92.1 U4.92(GPIO49)
GPIO50: R91.1 U4.93(GPIO50)
GPIO51: R89.1 U4.94(GPIO51)
GPIO52: R87.1 U4.95(GPIO52)
GPIO53: R79.1 R85.2 U4.97(GPIO53)
GPIO54: R76.1 R80.2 U4.98(GPIO54)
I2S_ASDOUT: R44.1 U3.7(ASDOUT)
I2S_DSDIN: R45.1 U3.9(DSDIN)
I2S_LRCK: C29.1 R27.1 U3.8(LRCK)
I2S_MCLK: C23.1 R43.1 U3.2(MCLK)
I2S_SCLK: C26.1 R26.1 U3.6(SCLK/DMIC_SCL)
MDC: R133.2 R160.2 U8.22(MDC)
MDIO: R87.2 R163.2 U8.23(MDIO)
MICN: C34.1 R64.2 R65.1
MICP: C32.1 J7.1(+) R63.1 TP11.1
OUTN: C57.1 C58.1 R84.2
OUTP: C59.1 C60.1 R83.2
PA_CTRL: R79.2 R148.1 U10.1(CTRL)
PA_INL+: R147.2 U10.3(IN+)
PA_INL-: R146.2 U10.4(IN-)
PA_OUTL+: L3.2 U10.8(OUT+)
PA_OUTL-: L2.2 U10.5(OUT-)
PA_PVDD1: C63.1 C66.1 C67.2 R171.1 U10.6(VCC)
PHY_3V3: C108.1 C109.1 C112.1 C114.1 J17.12(YLED+) R141.1 R149.1 R155.1 R157.1 R160.1 R163.1 R164.1 R167.1 R168.1 R213.2 U8.13(VDD_IO) U8.31(AVDD33)
PHY_AD0: R141.2 R222.2 U8.11(LED0/PHY_AD0)
PHY_AD3: J17.9(GLED+) R140.2 U8.12(LED3/PHY_AD3)
PHY_ISET: R165.1 U8.25(ISET)
PHY_RSTN: R89.2 R166.1 R167.2 U8.32(RESET_N)
PHY_TESTON: R164.2 U8.24(TEST_ON)
RD+: J17.3(RXD+) U8.27(MDI_RP)
RD-: J17.6(RXD-) U8.26(MDI_RN)
RMII_CLK: R91.2 R139.1 R142.1
RMII_RXD0: R132.2 R144.1
RMII_RXD1: R115.2 R143.1
RMII_RXDV: R114.2 R150.1
RMII_TXD0: R117.2 U8.9(TXD0)
RMII_TXD1: R135.2 U8.8(TXD1)
RMII_TXEN: R92.2 U8.5(TXEN)
RXER: R156.1 R157.2 U8.21(RXER/INTR_32)
SD1_CLK: D6.2 J21.5(CLK) R103.2 TP15.1
SD1_CMD: D4.2 J21.3(CMD) R17.2 R102.2 TP14.1
SD1_D0: D11.2 J21.7(DATA0) R36.2 R122.2 TP19.1
SD1_D1: D10.2 J21.8(DATA1) R34.2 R110.2 TP18.1
SD1_D2: D8.2 J21.1(DATA2) R21.2 R108.2 TP17.1
SD1_D3: D7.2 J21.2(CD/DATA3) R19.2 R107.2 TP16.1
SD1_VDD: C14.1 C15.1 D3.2 J21.4(VDD) Q8.3(D) R16.1 TP13.1
SD2_CLK: R12.2 R23.1 TP5.1 U1.25(IO19)
SD2_CMD: R11.2 R40.1 TP4.1 U1.24(IO18)
SD2_D0: R6.2 R25.1 TP9.1 U1.26(IO20)
SD2_D1: R5.2 R42.1 TP8.1 U1.27(IO21)
SD2_D2: R3.2 R24.1 TP7.1 U1.28(IO22)
SD2_D3: R1.2 R41.1 TP6.1 U1.29(IO23)
SD_DET: D5.2 J21.9(CD) R16.2 TP10.1
SD_PWRN: Q8.1(G) R229.2 R230.1 R231.2
TD+: J17.1(TXD+) U8.30(MDI_TP)
TD-: J17.2(TXD-) U8.29(MDI_TN)
TXER: R168.2 R169.1 U8.1(TXER/FXSD)
USB0_5V: C76.1 D20.2 J20.3(A4_VBUS) J20.4(B9_VBUS) J20.13(B4_VBUS) J20.14(A9_VBUS) Q2.1(1E) Q3.3(D)
USB1_5V: C117.1 D19.2 J19.3(A4_VBUS) J19.4(B9_VBUS) J19.13(B4_VBUS) J19.14(A9_VBUS) Q6.1(1E) Q7.3(D)
USB1P1_N: D17.2 J19.7(B7_DN2) J19.9(A7_DN1) R104.2
USB1P1_N_2: D24.2 J20.7(B7_DN2) J20.9(A7_DN1) R113.2
USB1P1_P: D18.2 J19.8(A6_DP1) J19.10(B6_DP2) R105.2
USB1P1_P_2: D23.2 J20.8(A6_DP1) J20.10(B6_DP2) R131.2
USB2_5V: C110.1 D13.2 J15.3(A4_VBUS) J15.4(B9_VBUS) J15.13(B4_VBUS) J15.14(A9_VBUS) Q4.3(D) Q5.1(1E)
USB_5V: C79.1 C80.1 Q2.4 Q3.2(S) Q4.2(S) Q5.4 Q6.4 Q7.2(S) SW3.2
USB_DM: R221.2 U4.49(DM)
USB_DM_A: D22.2 J18.2(D-) R178.2 R221.1
USB_DM_C: D14.2 J15.7(B7_DN2) J15.9(A7_DN1) R178.1
USB_DP: R220.2 R234.1 U4.50(DP)
USB_DP_A: D21.2 J18.3(D+) R179.2 R220.1
USB_DP_C: D16.2 J15.8(A6_DP1) J15.10(B6_DP2) R179.1
VMID: C37.2 U3.16(VMID)
XTAL_N: R70.1 U4.99(XTAL_N)
XTAL_P: R67.1 U4.100(XTAL_P)
N16934509: C28.1 R67.2 Y2.1(XIN)
N16934523: C45.1 R70.2 Y2.3(XOUT)
N17578381: D12.1(ANODE) R175.1
N18064827: C98.1 C99.1 C100.1 R233.1 U4.51(VDD_USBPHY)
N18110516: C19.1 R58.1 R61.2 Y1.2
N18110531: C18.1 R58.2 R59.2 Y1.1
N18193754: C54.1 R127.2 U7.4(VIN)
N18193822: L1.1 U7.3(SW)
N18248775: R151.2 TP28.1 U9.3(FLG)
N18251395: Q6.2 Q6.5 Q6.6 R224.2
N18251818: Q6.3 Q7.1(G) R225.2
N18253640: Q5.2 Q5.5 Q5.6 R217.2
N18253683: Q4.1(G) Q5.3 R216.2
N18255493: J15.6(A5_CC1) R180.2
N18255499: J15.12(B5_CC2) R182.2
N18256275: J19.6(A5_CC1) R184.2
N18256281: J19.12(B5_CC2) R183.2
N18262730: C69.2 R170.1 R172.2 U11.5(FB)
N18262736: C69.1 C70.1 L4.2 R172.1 R174.1 TP30.1
N18262777: R173.2 U11.1(EN/PG)
N18262785: L4.1 U11.3(SW)
N18266990: C115.1 J17.4(TXCT)
N18266994: C116.1 J17.5(RXCT)
N18267072: J17.10(GLED-) R223.1
N18267076: J17.11(YLED-) R222.1
N18267340: R143.2 U8.17(RXD1)
N18267342: R144.2 U8.18(RXD0)
N18267344: R150.2 U8.19(RXDV/CRS_DV/FX_HEN)
N18267350: R139.2 U8.14(RXCLK/50M_CLKO)
N18267444: C111.1 C113.1 U8.28(REGOUT)
N18267472: R142.2 U8.10(TXCLK/50M_CLKI)
N18299901: C32.2 U3.18(MIC1P/DMIC_SDA)
N18299903: C34.2 U3.17(MIC1N)
N18300035: C24.1 R52.2 U3.1(CCLK)
N18300076: C27.1 R62.2 U3.19(CDATA)
N18300564: J7.2(-) R64.1 R66.1 TP20.1
N18300580: C36.2 R63.2 R65.2 R73.1
N18302373: C40.2 C41.1 U3.13(OUTN)
N18302385: C38.1 C39.2 U3.12(OUTP)
N18302434: C40.1 R84.1
N18302436: C39.1 R83.1
N18379689: C64.1 R158.2 R159.1 Y3.1(XIN)
N18379734: C68.1 R159.2 R161.2 Y3.3(XOUT)
N18399134: Q2.2 Q2.5 Q2.6 R176.2
N18399180: Q2.3 Q3.1(G) R177.2
N18405255: J20.6(A5_CC1) R185.2
N18405261: J20.12(B5_CC2) R186.2
N18412230: J5.11(SCL0) R9.2
N18412242: J5.12(SDA0) R8.2
N18422156: C62.1 U10.2(BYPASS)
N18423897: C77.2 C78.2 J16.1 L3.1 TP32.1
N18423915: C78.1 C81.1 J16.2 L2.1 TP31.1
N18424033: C59.2 R147.1
N18424043: C58.2 R146.1
N18497724: J9.13(SCL0) R106.2
N18497727: J9.14(SDA0) R101.2
N18604768: R226.1 U5.3(EN)
N18792940: C118.1 R232.1 U4.54(VDD_HP_1)

Pads without a net: J1 27 28; J2 2; J5 16 17 18 19 20 21 22 23 24 25 26 27 28 29 30; J9 16 17 18 19 20 21 22 23 24 25 26 27 28 29 30; J15 5 11; J17 7; J19 5 11; J20 5 11; SW1 2 4; SW2 2 4; SW3 3; U1 4 6 7 9 10 12 13 15 16 17 18 19 20 21 32 33 34 35; U5 4; U8 6 7 15 16

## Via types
v1: diameter 0.508, hole 0.254, TOP to BOTTOM, 1247 vias

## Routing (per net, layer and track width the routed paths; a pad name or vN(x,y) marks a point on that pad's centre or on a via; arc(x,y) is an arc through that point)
A3V3: length 17.5
  TOP w0.381: v1(66.51,47.42) R68.2 ; U5.5 50.83,46.54 51.58,47.28 53.53,47.28 C33.1 55.32,46.78 C31.1 57.2,46.76 v1(57.22,46.78)
  BOTTOM w0.381: v1(66.51,47.42) 65.88,46.78 v1(57.22,46.78)
AGND:
  vias: v1(50.84,57.25) v1(50.8,55.04) v1(51.68,53.55) v1(52.9,58.54) v1(53.65,53.95) v1(54.79,52.5) v1(54.99,54.6) v1(55.08,57.44) v1(55.95,56.02) v1(56.02,51.17) v1(56.26,58.56) v1(56.73,47.36) v1(56.78,49.93) v1(56.76,45.18) v1(56.76,43.3) v1(56.8,40.29) v1(56.89,38.83) v1(57.53,53.71) v1(57.5,49.93) v1(57.57,46.18) v1(57.7,56.99) v1(58.21,49.93) v1(58.63,52.48) v1(58.82,51.16) v1(58.77,40.58) v1(59.41,41.94) v1(59.46,58.17) v1(59.87,44.01) v1(60.21,47.36) v1(60.26,41.94) v1(60.4,45.2) v1(60.46,54.41) v1(60.62,58.59) v1(61.04,56.4) v1(61.13,52.64) v1(61.13,51.84) v1(61.7,46.18) v1(62.11,57.53) v1(62.07,55.44) v1(62.09,41.95) v1(62.44,46.18) v1(62.64,38.85) v1(62.8,42.62) v1(63.05,56.54) v1(63.36,47.36) v1(63.48,49.76) v1(63.87,58.63) v1(64.15,50.04) v1(64.33,52.85) v1(64.61,41.2) v1(64.86,47.36) v1(65.34,56.19) v1(65.32,51.86) v1(65.32,50.94) v1(65.32,42.92) v1(65.33,42.07) v1(65.51,38.89) v1(66.18,51.86) v1(66.21,50.94) v1(66.27,56.25) v1(66.46,48.12) v1(66.65,58.63) v1(66.7,46.73) v1(66.97,49.24) v1(67.02,44.72) v1(67.02,43.69) v1(67.15,40.33) v1(67.42,52.9) v1(67.97,56.16) v1(68,41.28) v1(68.09,45.02) v1(68.35,49.38) v1(68.37,42.78) v1(68.48,46.85) v1(68.77,45.05) v1(68.86,48.2) v1(69.6,55.6) v1(69.82,42.94) v1(70.04,54.18) v1(70.07,48.25) v1(70.72,52.54) v1(70.7,51.64) v1(70.73,48.95) v1(70.7,46.32) v1(70.77,53.44) v1(71.25,44.55) v1(72.74,46.35) v1(72.74,42.89) v1(73.17,53.81) v1(73.24,48.16) v1(73.26,50.29) v1(74.41,42.93) v1(74.63,52.05) v1(75.54,49) v1(75.49,45.2) v1(76.29,53.8) v1(76.48,50.12) v1(76.55,44.96) v1(77.22,50.74) v1(77.22,44.34) v1(77.91,50.06) v1(77.88,44.95) v1(78.35,42.99) v1(79.45,53.84) v1(79.48,52.02) v1(80.81,45.32) v1(81.05,49.67) v1(82.13,53.79) v1(82.1,47.54) v1(82.39,42.99) v1(82.85,50.7) v1(82.88,44.41) v1(84.01,45.62) v1(84.1,52.66) v1(84.43,49.51) v1(84.76,42.95) v1(86.99,52.03) v1(87.14,49.37) v1(87.11,45.67) v1(87.06,43.01)
AVDD: length 3.5
  TOP w0.254: 67.73,50.1 67.73,50.35 67.48,50.6 U3.11
  TOP w0.381: 67.73,50.1 67.73,49.14 68.03,48.83 C35.2 R68.1
DVDD: length 4.3
  TOP w0.254: U3.3 63.79,51.4 63.56,51.17 63.74,51 U3.4
  TOP w0.381: 63.56,51.17 63.21,51.17 C22.1 C21.1 R51.2
GND: length 210.7
  TOP w0.127: 25.16,9.36 v1(25.16,9.92) ; 26.64,9.36 v1(26.64,9.92)
  TOP w0.254: J15.1 22.07,7.03 22.22,7.18 22.37,7.03 J15.2 ; J20.16 58.85,7.2 58.69,7.36 58.55,7.21 J20.15 ; J19.16 43.81,7.1 43.63,7.28 43.51,7.16 J19.15 ; J20.2 52.45,7.1 52.29,7.25 52.15,7.11 J20.1 ; J15.15 28.47,7.15 28.59,7.28 28.77,7.11 J15.16 ; J19.2 37.41,7.05 37.25,7.21 37.11,7.06 J19.1
  TOP w0.508: v1(21.99,7.71) 22.22,7.48 22.22,7.18 ; v1(36.92,7.74) 37.25,7.41 37.25,7.21 ; v1(28.59,7.71) 28.59,7.28 ; 52.29,7.25 52.29,7.38 v1(51.86,7.81) ; v1(58.69,7.69) 58.69,7.36 ; v1(43.63,7.71) 43.63,7.28
  TOP w0.635: H2.1 64.33,70.5 ; H2.1 61.5,67.67 ; H2.1 58.67,70.5 ; 58.67,21.5 H4.1 ; H4.1 61.5,24.33 ; H4.1 64.33,21.5 ; H4.1 61.5,18.67 ; 3.5,18.67 H3.1 ; H3.1 6.33,21.5 ; H3.1 3.5,24.33 ; 57.85,69.23 J1.39 56.63,68.01 ; 3.5,67.67 H1.1 6.33,70.5 ; J17.8 77.97,18.75 ; J17.8 79.05,17.67 ; J17.8 77.97,16.59 ; J17.8 76.89,17.67 ; 12.49,12.34 J18.4 ; J18.4 13.48,11.35 ; J18.4 14.47,12.34 ; J18.4 13.48,13.33
  GND w0.635: H2.1 64.33,70.5 ; H2.1 61.5,67.67 ; H2.1 58.67,70.5 ; H4.1 61.5,24.33 ; H4.1 58.67,21.5 ; H4.1 64.33,21.5 ; H4.1 61.5,18.67 ; 49.01,72.2 49.01,72.38 48.31,73.08 ; 49.01,72.2 J1.34 ; 49.01,72.2 49.81,73 ; 70.18,69.65 J2.4 70.06,67.53 ; 43.93,72.04 J1.30 ; 43.93,72.04 43.93,72.19 44.67,72.93 ; 43.93,72.04 42.95,73.02 ; J17.8 79.05,17.67 ; J17.8 77.97,18.75 ; J17.8 76.89,17.67 ; J17.8 77.97,16.59 ; 37.77,68.15 J1.25 40.05,68.03 ; 23.61,71.96 23.61,72.17 24.43,72.99 ; 23.61,71.96 22.61,72.96 ; 23.61,71.96 J1.14 ; 3.5,18.67 H3.1 ; H3.1 6.33,21.5 ; H3.1 3.5,24.33 ; 12.49,12.34 J18.4 ; J18.4 13.48,13.33 ; J18.4 13.48,11.35 ; J18.4 14.47,12.34 ; 30.41,73.02 31.23,72.19 ; 31.23,72.19 J1.20 ; 31.23,72.19 31.23,72.28 31.99,73.04 ; 6.33,70.5 H1.1 3.5,67.67 ; 13.45,71.82 13.45,72.17 14.34,73.07 ; 13.45,71.82 J1.6 ; 13.45,71.82 12.31,72.96 ; 57.85,69.23 J1.39 56.63,68.01 ; 17.39,68.09 J1.9 19.59,68.17
  POWER w0.635: H3.1 3.5,24.33 ; H3.1 6.33,21.5 ; H3.1 3.5,18.67 ; 58.67,21.5 H4.1 ; H4.1 64.33,21.5 ; H4.1 61.5,18.67 ; 56.63,68.01 J1.39 57.85,69.23 ; 12.49,12.34 J18.4 ; J18.4 14.47,12.34 ; J18.4 13.48,13.33 ; J18.4 13.48,11.35 ; 77.97,16.59 J17.8 ; J17.8 77.97,18.75 ; J17.8 79.05,17.67 ; J17.8 76.89,17.67 ; 61.5,67.67 H2.1 ; H2.1 58.67,70.5 ; H2.1 64.33,70.5
  BOTTOM w0.127: v1(70.32,38.06) 70.4,38.14 D11.1 ; D6.1 70.35,36.9 v1(70.3,36.85) ; v1(70.32,39.46) 70.4,39.39 D10.1 ; D7.1 70.4,32.94 v1(70.25,33.09) ; D8.1 70.81,30.9 v1(71.09,30.62) ; D4.1 v1(70.27,34.18) ; D3.1 v1(70.27,35.43)
  BOTTOM w0.635: 58.67,70.5 H2.1 ; H2.1 64.33,70.5 ; H2.1 61.5,67.67 ; H3.1 6.33,21.5 ; H3.1 3.5,18.67 ; H3.1 3.5,24.33 ; 61.5,18.67 H4.1 ; H4.1 58.67,21.5 ; H4.1 61.5,24.33 ; H4.1 64.33,21.5 ; 12.35,12.34 J18.4 ; J18.4 14.61,12.34 ; J18.4 13.48,11.21 ; J18.4 13.48,13.47 ; 3.5,67.67 H1.1 6.33,70.5 ; J17.8 79.05,17.67 ; J17.8 77.97,16.59 ; J17.8 77.97,18.75 ; J17.8 76.89,17.67 ; 57.85,69.23 J1.39 56.63,68.01
  vias: v1(0.84,68.8) v1(0.84,65.8) v1(0.78,62.32) v1(0.78,46.74) v1(0.78,40.9) v1(0.78,36.49) v1(0.8,31.89) v1(0.85,27.73) v1(0.89,23.59) v1(0.87,19.71) v1(0.87,16.35) v1(0.85,13.08) v1(2.21,41.23) v1(2.16,37.06) v1(2.23,32.73) v1(2.37,62.4) v1(2.78,45.33) v1(2.94,42.79) v1(2.98,57.5) v1(3.27,16.73) v1(3.39,65.76) v1(3.42,54.73) v1(3.41,52.58) v1(3.74,14.49) v1(3.89,15.47) v1(4.06,59.5) v1(4.11,56.52) v1(4.12,53.38) v1(4.14,47.51) v1(4.09,17.76) v1(4.15,50.52) v1(4.19,35.45) v1(4.17,28.37) v1(4.32,45.85) v1(4.63,12.87) v1(5.05,38.42) v1(5.57,64.96) v1(5.64,41.61) v1(5.88,39.87) v1(5.95,34.81) v1(5.93,28.93) v1(6.09,68.46) v1(6.29,73.03) v1(6.54,25.23) v1(6.58,62.5) v1(6.58,18.41) v1(6.73,59.53) v1(6.73,53.43) v1(6.73,50.51) v1(6.73,47.5) v1(6.92,56.04) v1(6.89,21.42) v1(6.91,10.52) v1(6.98,43.21) v1(7.22,41.09) v1(7.28,45.86) v1(7.54,53.99) v1(7.47,51.98) v1(7.5,49.76) v1(7.52,48.29) v1(7.48,44.64) v1(7.56,16.32) v1(7.69,67.74) v1(7.94,55.72) v1(8.49,13.57) v1(8.63,27.71) v1(8.55,15.03) v1(8.74,17.74) v1(8.96,41.7) v1(9.11,19.76) v1(9.24,60.34) v1(9.19,45.88) v1(9.16,44.86) v1(9.31,63.17) v1(9.36,48.63) v1(9.45,61.37) v1(9.6,73.15) v1(9.55,65.1) v1(9.74,68.23) v1(9.78,59.3) v1(9.82,35.22) v1(9.8,32.22) v1(9.82,29.24) v1(9.78,26.22) v1(9.9,43.42) v1(9.92,22.57) v1(10.01,56.68) v1(9.99,11.29) v1(10.1,53.95) v1(10.16,62.29) v1(10.3,44.86) v1(10.77,19.79) v1(11.2,49.41) v1(11.19,23.66) v1(11.2,21.43) v1(11.22,17.25) v1(11.45,58.97) v1(11.43,15.08) v1(11.59,52.5) v1(11.59,46.93) v1(11.57,13.5) v1(11.94,66.18) v1(12.13,55.96) v1(12.16,44.26) v1(12.25,22.53) v1(12.45,60.62) v1(12.4,41.99) v1(12.39,35.22) v1(12.44,29.25) v1(12.41,26.23) v1(12.39,20.21) v1(12.46,40.26) v1(12.47,38.51) v1(12.56,31.52) v1(12.83,10.56) v1(12.86,62.68) v1(12.99,59.85) v1(13.05,53.61) v1(13,18.78) v1(13.11,67.77) v1(13.12,51.65) v1(13.1,49.76) v1(13.2,45.3) v1(13.44,47.18) v1(13.45,73.21) v1(13.52,36.41) v1(13.5,31.32) v1(13.61,39.63) v1(13.57,29.95) v1(13.8,37.86) v1(13.85,28.22) v1(13.89,21.58) v1(14.04,57.37) v1(14.05,26.44) v1(14.14,42.31) v1(14.21,13.48) v1(14.25,24.5) v1(14.42,64.48) v1(14.49,40.96) v1(14.48,17.8) v1(14.73,22.52) v1(14.84,43.67) v1(14.88,15.17) v1(15.05,29.82) v1(15.15,37.4) v1(15.17,31.26) v1(15.33,36.21) v1(15.29,18.66) v1(15.45,45.15) v1(15.46,49.55) v1(15.54,47.44) v1(15.64,21.25) v1(15.66,65.79) v1(16.07,53.33) v1(16.11,35.07) v1(16.14,33.56) v1(16.09,30.62) v1(16.07,28.46) v1(16.15,18.76) v1(16.2,26.51) v1(16.48,24.24) v1(16.81,46.12) v1(16.84,13.48) v1(16.88,44.62) v1(17.25,58.85) v1(17.24,37.63) v1(17.17,22.57) v1(17.28,73.17) v1(17.28,61.34) v1(17.29,49.6) v1(17.36,52.59) v1(17.47,34.64) v1(17.59,47.06) v1(17.61,32.71) v1(17.55,29.96) v1(17.58,27.1) v1(17.62,21.12) v1(17.94,66.14) v1(17.88,25.44) v1(18.33,43.6) v1(18.26,22.36) v1(18.36,21.12) v1(18.53,67.77) v1(18.51,36.46) v1(18.7,61.42) v1(18.75,58.91) v1(18.84,18.76) v1(19,30.89) v1(19.04,27.85) v1(19.02,24.19) v1(19.15,12.02) v1(19.26,64.39) v1(19.45,52.7) v1(19.37,32.71) v1(19.59,47.44) v1(19.8,73.08) v1(19.88,33.9) v1(19.93,15.17) v1(20.09,23.08) v1(20.14,21.09) v1(20.16,42.33) v1(20.18,40.15) v1(20.18,39.51) v1(20.44,30.94) v1(20.36,9.38) v1(20.48,27.89) v1(20.67,45.66) v1(20.72,18.73) v1(20.87,40.15) v1(21.11,24.55) v1(21.17,42.84) v1(21.28,10.09) v1(21.25,8.35) v1(21.38,13.38) v1(21.56,16.46) v1(21.71,21.76) v1(21.83,42.84) v1(22.06,62.74) v1(22.15,64.43) v1(22.23,39.78) v1(22.52,45.58) v1(22.5,18.76) v1(22.47,11.22) v1(22.53,4.27) v1(22.72,24.87) v1(22.79,34.88) v1(22.85,45) v1(22.85,44.29) v1(22.88,42.1) v1(22.88,41.39) v1(22.85,40.17) v1(23.03,67.82) v1(23.03,61.95) v1(22.96,14.61) v1(23.21,45.56) v1(23.17,27.61) v1(23.34,18.76) v1(23.61,73.21) v1(23.59,42.84) v1(23.65,5.68) v1(23.77,60.24) v1(23.78,14.15) v1(24.07,21.61) v1(24.13,18) v1(24.13,17.11) v1(24.13,10.2) v1(24.18,38.88) v1(24.58,40.15) v1(24.62,35.25) v1(24.62,33.92) v1(24.77,15.18) v1(24.95,63.69) v1(24.88,42.84) v1(24.88,5.02) v1(25,7.9) v1(25.06,22.52) v1(25.54,43.78) v1(25.54,41.95) v1(25.54,41.04) v1(25.54,39.44) v1(25.54,38.78) v1(25.54,38.14) v1(25.49,4.26) v1(25.59,59.9) v1(25.57,44.64) v1(25.82,19.62) v1(25.77,17.67) v1(25.94,64.2) v1(26.06,61.81) v1(26.2,45.58) v1(26.17,15.9) v1(26.56,5.1) v1(26.76,67.82) v1(27.02,42.84) v1(27.02,40.15) v1(27.12,55.59) v1(27.18,32.55) v1(27.42,72.98) v1(27.42,5.72) v1(27.56,25.87) v1(27.68,42.84) v1(27.68,40.15) v1(27.88,10.82) v1(27.97,62.13) v1(27.98,32.48) v1(28.02,27.6) v1(28.06,65.5) v1(28.1,19.66) v1(28.26,39.61) v1(28.31,4.27) v1(28.39,56.77) v1(28.36,43.83) v1(28.36,42.1) v1(28.4,9.55) v1(28.64,11.32) v1(28.71,13.38) v1(29.15,15.87) v1(29.45,67.96) v1(29.48,47.56) v1(29.62,8.46) v1(29.73,36.41) v1(29.67,35.12) v1(29.8,27.91) v1(29.9,64.79) v1(29.91,57.19) v1(29.96,48.05) v1(30.03,25.82) v1(30,22.39) v1(30.34,43.63) v1(30.28,17.82) v1(30.5,68.01) v1(30.47,46.14) v1(30.55,19.71) v1(30.52,11.55) v1(30.64,27.43) v1(30.7,33.67) v1(30.74,22.39) v1(30.89,65.52) v1(30.89,59.08) v1(30.85,44.87) v1(31.05,38.93) v1(31.09,35.11) v1(31.23,73.21) v1(31.44,19.27) v1(31.5,27.41) v1(31.64,48.4) v1(31.66,49.67) v1(31.69,38.29) v1(31.66,13.46) v1(31.77,44.87) v1(32.03,9.92) v1(32.1,51.4) v1(32.12,50.51) v1(32.06,30.25) v1(32.06,29.49) v1(32.2,45.58) v1(32.17,42.69) v1(32.38,49.09) v1(32.38,15.33) v1(32.5,52.29) v1(32.53,46.6) v1(32.53,37.43) v1(32.55,65.18) v1(32.55,55.69) v1(32.93,47.92) v1(32.88,8.17) v1(32.97,58.16) v1(32.99,44.8) v1(33.06,60.29) v1(33.09,42.79) v1(33.11,41.95) v1(33.34,45.56) v1(33.43,25.9) v1(33.48,30.1) v1(33.51,19.46) v1(33.59,52.31) v1(33.63,32.55) v1(33.72,11.51) v1(33.85,41.29) v1(34.2,48.81) v1(34.33,46.57) v1(34.36,40.5) v1(34.51,67.96) v1(34.66,49.88) v1(34.74,30.01) v1(34.71,13.26) v1(34.79,52.29) v1(35.02,40.45) v1(35.09,73.13) v1(35.17,48.81) v1(35.2,8.77) v1(35.36,31.56) v1(35.41,16.35) v1(35.75,45.53) v1(35.83,19.47) v1(35.82,9.5) v1(35.93,48) v1(35.93,46.6) v1(35.87,11.52) v1(35.96,52.26) v1(36.12,22.39) v1(36.11,8.16) v1(36.2,64.93) v1(36.21,41.47) v1(36.31,29.31) v1(36.35,27.08) v1(36.49,44.9) v1(36.49,44.01) v1(36.49,43.14) v1(36.49,42.26) v1(36.72,59.82) v1(36.9,51.93) v1(36.92,50.38) v1(36.9,48.99) v1(36.87,28.17) v1(37.63,47.64) v1(37.61,45.43) v1(37.61,43.22) v1(37.56,25.87) v1(37.57,4.31) v1(37.71,15.57) v1(38.09,31.58) v1(38.17,67.99) v1(38.37,19.7) v1(38.69,5.72) v1(38.87,10.1) v1(39.3,11.98) v1(39.74,65.99) v1(39.74,28.04) v1(39.73,7.74) v1(39.78,25.59) v1(39.82,10.1) v1(39.82,9.18) v1(39.92,30.79) v1(39.88,5.02) v1(40.08,73.13) v1(40.33,17.21) v1(40.3,14.8) v1(40.55,67.99) v1(40.69,4.28) v1(41.04,37.53) v1(41.1,19.7) v1(41.16,26.7) v1(41.28,29.48) v1(41.43,64.9) v1(41.44,22.46) v1(41.65,39.53) v1(41.63,30.79) v1(41.65,5.15) v1(41.66,10.24) v1(41.66,9.11) v1(42.17,14.56) v1(42.5,5.74) v1(42.6,12.64) v1(42.65,10.19) v1(42.71,28.13) v1(42.84,68.02) v1(42.78,30.98) v1(42.9,58.44) v1(42.85,15.99) v1(43.04,55.73) v1(42.99,52.78) v1(42.95,43.3) v1(43.02,40.03) v1(43.08,49.7) v1(43.32,65.98) v1(43.3,46.92) v1(43.34,9.5) v1(43.32,4.3) v1(43.4,32.31) v1(43.74,24.82) v1(43.66,17.2) v1(43.84,42.37) v1(43.93,73.21) v1(43.92,59.43) v1(44.01,29.39) v1(44.15,38.23) v1(44.15,19.7) v1(44.38,36.54) v1(44.71,32.35) v1(44.99,12.92) v1(45.15,10.15) v1(45.41,22.49) v1(45.62,24.83) v1(45.71,67.99) v1(45.69,61.05) v1(45.75,58.63) v1(45.75,15.65) v1(45.72,13.49) v1(45.79,8.16) v1(45.9,49.88) v1(45.94,46.43) v1(45.9,19.01) v1(45.9,18.24) v1(46,60.02) v1(45.98,54.23) v1(45.95,40.39) v1(46.03,38.17) v1(46.03,36.55) v1(46.04,32.35) v1(46.05,44.86) v1(46.23,17.53) v1(46.68,14.65) v1(46.79,20.93) v1(47.22,24.32) v1(47.53,15.63) v1(47.56,8.79) v1(47.86,73.14) v1(48.11,16.97) v1(48.16,9.2) v1(48.26,20.07) v1(48.33,13.44) v1(48.44,32.35) v1(48.48,58.11) v1(48.5,55.43) v1(48.5,52.23) v1(48.54,26.58) v1(48.63,22.58) v1(48.72,41.34) v1(48.8,47.2) v1(48.82,45.01) v1(49.15,37.81) v1(49.18,15.73) v1(49.27,60.01) v1(49.33,40.4) v1(49.43,64.85) v1(49.56,56.64) v1(49.56,17.02) v1(50,53.44) v1(50,39.63) v1(49.97,21) v1(49.95,8.97) v1(50.21,49.93) v1(50.18,36.57) v1(50.41,61.05) v1(50.37,58.56) v1(50.41,32.35) v1(50.47,47.21) v1(50.61,15.13) v1(50.69,8.33) v1(50.85,12.28) v1(51.11,65.71) v1(51.21,51.16) v1(51.22,9.11) v1(51.43,25.67) v1(51.63,23.61) v1(51.6,20.06) v1(51.67,59.74) v1(51.81,44.76) v1(51.78,43.93) v1(51.81,41.25) v1(51.93,39.75) v1(52.12,61.13) v1(52.1,11.75) v1(52.51,41.85) v1(52.62,39.77) v1(52.61,4.31) v1(52.71,38.26) v1(52.76,12.46) v1(53.23,52.39) v1(53.42,73.18) v1(53.44,11.73) v1(53.72,5.71) v1(53.8,38.26) v1(53.83,23.96) v1(53.84,10.19) v1(54.03,45.1) v1(53.98,32.18) v1(54.02,25.91) v1(54.22,49.95) v1(54.18,39.65) v1(54.37,66.94) v1(54.37,51.17) v1(54.42,9.18) v1(54.58,65.33) v1(54.59,4.99) v1(54.74,14.8) v1(54.73,10.29) v1(54.77,19.27) v1(54.93,49.95) v1(54.89,44.33) v1(54.91,21.22) v1(55.62,67.87) v1(55.62,49.95) v1(55.63,44.33) v1(55.58,41.58) v1(55.69,59.76) v1(55.68,4.26) v1(55.91,26.55) v1(55.97,64.94) v1(55.97,38.19) v1(56.21,18.9) v1(56.21,14.9) v1(56.21,10.29) v1(56.56,9.18) v1(56.71,7.74) v1(57.52,5.72) v1(57.6,25.33) v1(57.78,9.55) v1(58.04,70.5) v1(58.23,73.08) v1(58.42,67.01) v1(58.39,4.32) v1(58.83,24.11) v1(59.22,59.76) v1(59.41,17.11) v1(59.44,12.41) v1(59.53,63.05) v1(59.72,26.53) v1(60.18,37.71) v1(61.26,64.63) v1(61.48,67) v1(61.55,25.33) v1(61.61,8.51) v1(61.89,32.24) v1(62.54,9.38) v1(63.05,32.29) v1(63.29,64.94) v1(63.41,63.21) v1(63.44,59.69) v1(63.35,17.12) v1(63.47,26.58) v1(63.49,8.54) v1(63.55,73.12) v1(63.58,25.89) v1(63.63,12.45) v1(63.82,37.7) v1(63.97,66.64) v1(64.32,32.25) v1(64.48,69.38) v1(64.61,29.58) v1(64.79,63.46) v1(64.99,65.78) v1(65.17,36.95) v1(65.35,13.84) v1(65.55,67.41) v1(66.34,19.08) v1(66.34,16.58) v1(66.6,17.57) v1(66.68,38.42) v1(66.69,36.95) v1(67.16,64.56) v1(67.43,59.49) v1(67.8,17.59) v1(68.05,16.21) v1(68.19,26.18) v1(68.24,22.42) v1(68.25,73.19) v1(68.27,21.57) v1(68.3,20.48) v1(68.44,40.15) v1(68.53,30.84) v1(68.93,28.37) v1(69.1,20.08) v1(69.26,18.81) v1(69.28,13.71) v1(69.38,57.38) v1(69.42,23.47) v1(69.71,28.16) v1(69.84,41.38) v1(69.84,21.64) v1(69.9,20.78) v1(70.41,26.47) v1(70.41,25.48) v1(70.44,24.46) v1(70.53,65.42) v1(70.63,58.89) v1(70.56,56.28) v1(70.72,41.32) v1(70.93,18.89) v1(71.01,63.46) v1(71.12,70.32) v1(71.16,67.62) v1(71.2,21.59) v1(71.2,20.27) v1(71.35,26.44) v1(71.38,25.45) v1(71.35,24.44) v1(71.61,71.87) v1(71.8,30.62) v1(71.86,55.04) v1(71.93,13.71) v1(72.3,71.25) v1(72.34,36.59) v1(72.28,35.3) v1(72.29,26.44) v1(72.32,25.5) v1(72.32,24.46) v1(72.44,18.91) v1(72.38,16.31) v1(72.52,21.95) v1(72.57,20.3) v1(72.81,41.63) v1(72.81,40.74) v1(72.91,73.17) v1(72.94,69.45) v1(72.86,67.64) v1(72.85,64.67) v1(72.85,61.86) v1(73.48,20.6) v1(73.75,66.12) v1(73.84,60.9) v1(73.85,63.66) v1(74.22,71.19) v1(74.42,19.81) v1(74.53,23.52) v1(74.49,13.71) v1(74.63,64.38) v1(74.7,69.37) v1(74.73,66.51) v1(74.74,62.14) v1(75.14,55.07) v1(75.12,27.4) v1(75.16,59.58) v1(75.2,25.77) v1(75.31,67.55) v1(75.34,38.74) v1(75.4,41.61) v1(75.47,61.27) v1(75.54,36.48) v1(75.48,35.58) v1(75.48,15.72) v1(75.62,30.72) v1(75.61,28.95) v1(75.62,23.5) v1(75.76,65.52) v1(76.04,73.13) v1(76.06,25.82) v1(76.52,33.12) v1(76.61,21.26) v1(76.75,26.69) v1(76.77,73.13) v1(76.75,16.88) v1(76.9,66.55) v1(76.91,64.38) v1(76.9,62.16) v1(76.94,28.21) v1(76.99,22.95) v1(77.12,69.32) v1(77.14,21.98) v1(77.19,60.43) v1(77.16,25.91) v1(77.19,20.03) v1(77.22,18.81) v1(77.77,67.5) v1(77.83,26.77) v1(77.75,21.42) v1(78.31,69.31) v1(78.34,59.41) v1(78.3,55.07) v1(78.36,20.75) v1(78.51,15.85) v1(78.92,26.66) v1(79,61.13) v1(79.01,41.66) v1(79.06,66.56) v1(79.06,64.38) v1(79.06,62.14) v1(79.09,37.12) v1(79.1,30.95) v1(79.14,15.18) v1(79.31,67.62) v1(79.43,57.56) v1(79.39,20.7) v1(79.56,25.91) v1(79.87,69.33) v1(80.05,65.24) v1(80.08,63.54) v1(80.17,21.63) v1(80.33,73.14) v1(80.28,71.21) v1(80.27,56.35) v1(80.31,25.15) v1(80.32,24.2) v1(80.37,22.7) v1(80.39,17.52) v1(80.36,13.76) v1(80.94,69.18) v1(80.94,67.58) v1(80.94,65.98) v1(80.94,64.38) v1(80.94,62.78) v1(80.94,61.21) v1(80.92,59.58) v1(80.99,71.9) v1(81.44,29.17) v1(81.63,71.2) v1(81.64,55.1) v1(81.65,57.6) v1(81.8,41.61) v1(81.91,25.48) v1(82.16,13.76) v1(82.81,34.48) v1(82.91,10.3) v1(82.92,5.76) v1(82.9,0.87) v1(83.3,18.85) v1(83.48,24.36) v1(83.51,13.46) v1(83.71,39.86) v1(83.7,26.65) v1(84.36,14.35) v1(84.89,8.72) v1(85.08,3.8) v1(85.23,25.53) v1(85.26,40.95) v1(85.27,13.45) v1(86.78,1.31) v1(87.11,41.62) v1(87.14,35.96) v1(87.06,29.64) v1(87.09,23.8) v1(87.09,18.39) v1(87.09,12.64) v1(87.09,7.41)
